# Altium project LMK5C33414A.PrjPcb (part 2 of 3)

## Sheet LMK5C33414A_DUT.SchDoc
size 431 x 279 mm; Date: Not shown in title block; ApprovedBy: Not shown in title block; CheckedBy: Not shown in title block; Author: Not shown in title block; CompanyName: Not shown in title block; Engineer: Not shown in title block; Organization: Not shown in title block; Address1: Not shown in title block; Address2: Not shown in title block; Address3: Not shown in title block; Address4: Not shown in title block; DocumentNumber: 2; Revision: Use project parameter SCH_Rev; SheetNumber: 2; SheetTotal: 3; PageSetup: Record=PageOptions¦CenterHorizontal=True¦CenterVertical=True¦PrintScale=1.00¦XCorrection=1.00¦YCorrection=1.00¦PrintKind=0¦BorderSize=5000000¦LeftOffset=0¦BottomOffset=0¦Orientation=2¦PaperLength=1000¦PaperWidth=1000¦Scale=100¦PaperSource=15¦PrintQuality=600¦MediaType=1¦DitherType=10¦PaperKind=Letter¦PrintScaleMode=1
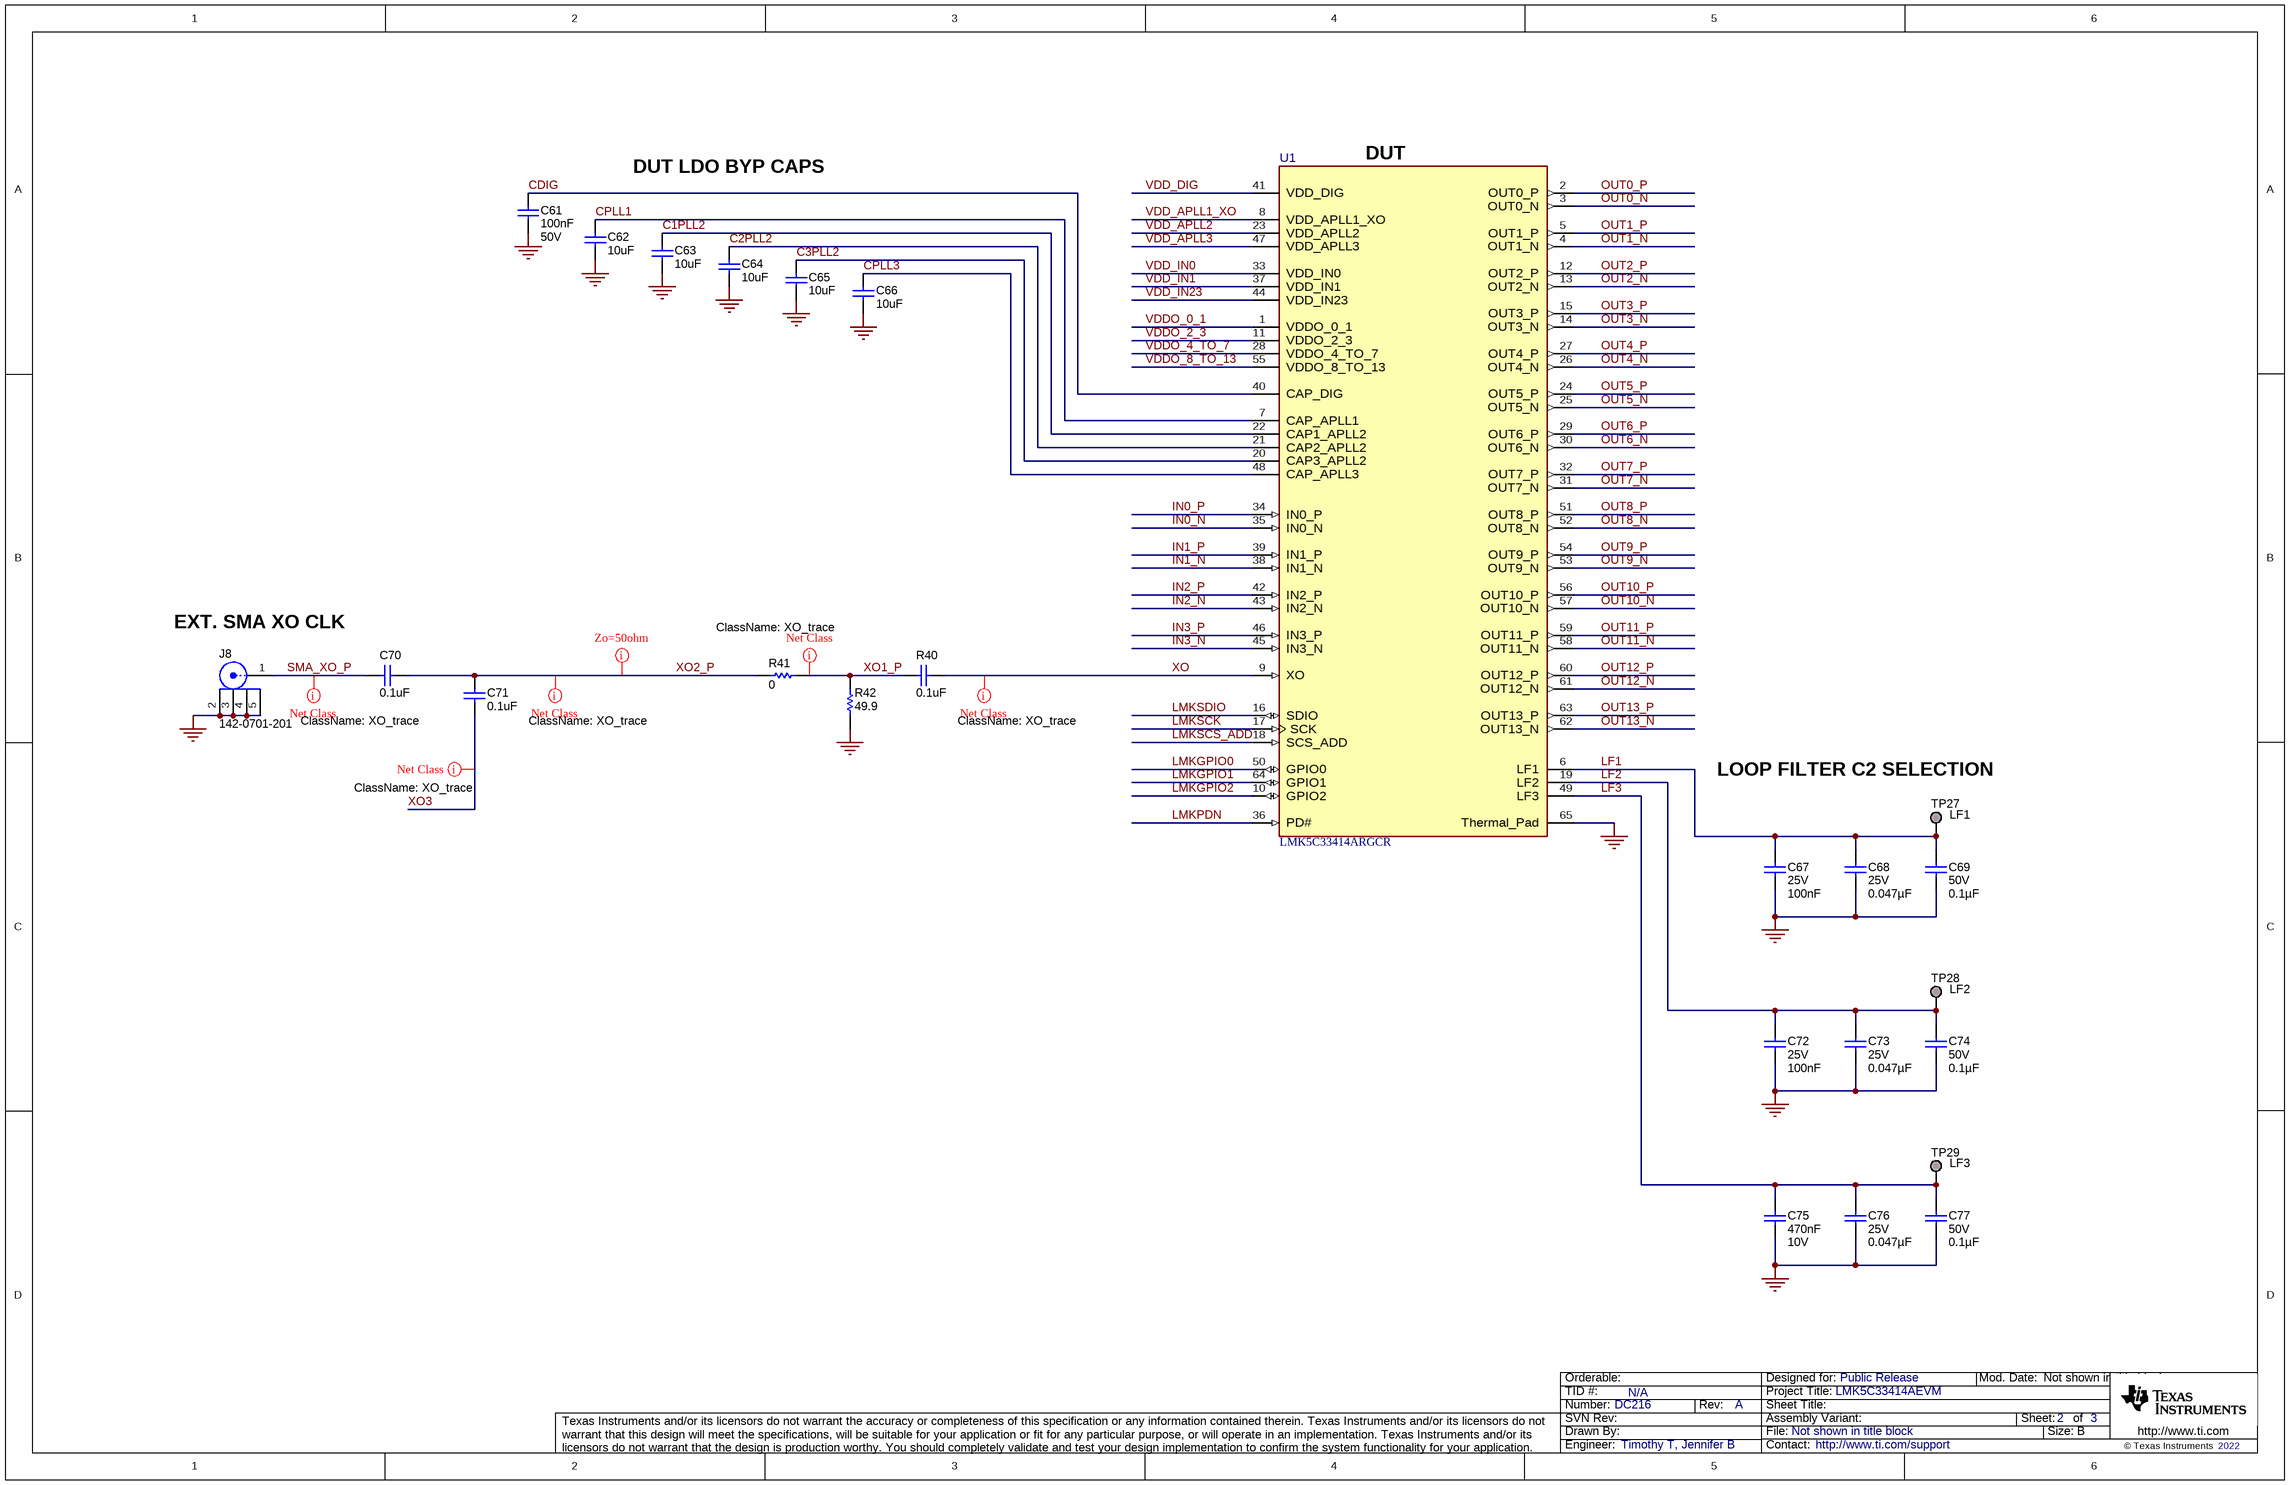
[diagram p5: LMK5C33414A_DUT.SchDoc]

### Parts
C61  Cap_F: 100nF  VDC_V: 50V  [0603L]  (hidden comment: C1608X7R1H104K080AA)
C62  ValueDisplayed: 10uF  [0603L]  (hidden comment: Capacitor)
C63  ValueDisplayed: 10uF  [0603L]  (hidden comment: Capacitor)
C64  ValueDisplayed: 10uF  [0603L]  (hidden comment: Capacitor)
C65  ValueDisplayed: 10uF  [0603L]  (hidden comment: Capacitor)
C66  ValueDisplayed: 10uF  [0603L]  (hidden comment: Capacitor)
C67  VDC_V: 25V  Cap_F: 100nF  [0603]  (hidden comment: C0603C104J3RACTU)
C68  VDC_V: 25V  ValueDisplayed: 0.047µF  [0805_150]  (hidden comment: C0805C473J3GACTU)
C69  VDC_V: 50V  ValueDisplayed: 0.1µF  [1210_280]  (hidden comment: C3225C0G1H104J250AA)
C70  ValueDisplayed: 0.1uF  [0603S]  (hidden comment: C0603C104J3RACTU)
C71  ValueDisplayed: 0.1uF  [0603S]  (hidden comment: C0603C104J3RACTU)
C72  VDC_V: 25V  Cap_F: 100nF  [0603]  (hidden comment: C0603C104J3RACTU)
C73  VDC_V: 25V  ValueDisplayed: 0.047µF  [0805_150]  (hidden comment: Capacitor)
C74  VDC_V: 50V  ValueDisplayed: 0.1µF  [1210_280]  (hidden comment: C3225C0G1H104J250AA)
C75  Cap_F: 470nF  VDC_V: 10V  [0603]  (hidden comment: GRM188R71A474KA61D)
C76  VDC_V: 25V  ValueDisplayed: 0.047µF  [0805_150]  (hidden comment: Capacitor)
C77  VDC_V: 50V  ValueDisplayed: 0.1µF  [1210_280]  (hidden comment: C3225C0G1H104J250AA)
J8  142-0701-201  [Johnson_142-0701-20x]
R40  ValueDisplayed: 0.1uF  [0603S]  (hidden comment: Capacitor)
R41  value 0  [0603S]  (hidden comment: Resistor)
R42  ValueDisplayed: 49.9  [0603S]  (hidden comment: Resistor)
TP27  LF1  [TP_SM_1MM]  (no BOM)
TP28  LF2  [TP_SM_1MM]  (no BOM)
TP29  LF3  [TP_SM_1MM]  (no BOM)
U1  LMK5C33414ARGCR  [RGC0064E-MFG]

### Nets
GND: C61.2 C62.2 C63.2 C64.2 C65.2 C66.2 C67.2 C68.1 C69.2 C72.2 C73.1 C74.2 C75.2 C76.1 C77.2 J8.2 J8.3 J8.4 J8.5 R42.1 U1.65(Thermal_Pad)
C1PLL2: C63.1 U1.22(CAP1_APLL2)
C2PLL2: C64.1 U1.21(CAP2_APLL2)
C3PLL2: C65.1 U1.20(CAP3_APLL2)
CDIG: C61.1 U1.40(CAP_DIG)
CPLL1: C62.1 U1.7(CAP_APLL1)
CPLL3: C66.1 U1.48(CAP_APLL3)
IN0_N: U1.35(IN0_N)
IN0_P: U1.34(IN0_P)
IN1_N: U1.38(IN1_N)
IN1_P: U1.39(IN1_P)
IN2_N: U1.43(IN2_N)
IN2_P: U1.42(IN2_P)
IN3_N: U1.45(IN3_N)
IN3_P: U1.46(IN3_P)
LF1: C67.1 C68.2 C69.1 TP27.1 U1.6(LF1)
LF2: C72.1 C73.2 C74.1 TP28.1 U1.19(LF2)
LF3: C75.1 C76.2 C77.1 TP29.1 U1.49(LF3)
LMKGPIO0: U1.50(GPIO0)
LMKGPIO1: U1.64(GPIO1)
LMKGPIO2: U1.10(GPIO2)
LMKPDN: U1.36(PD#)
LMKSCK: U1.17(SCK)
LMKSCS_ADD: U1.18(SCS_ADD)
LMKSDIO: U1.16(SDIO)
OUT0_N: U1.3(OUT0_N)
OUT0_P: U1.2(OUT0_P)
OUT1_N: U1.4(OUT1_N)
OUT1_P: U1.5(OUT1_P)
OUT2_N: U1.13(OUT2_N)
OUT2_P: U1.12(OUT2_P)
OUT3_N: U1.14(OUT3_N)
OUT3_P: U1.15(OUT3_P)
OUT4_N: U1.26(OUT4_N)
OUT4_P: U1.27(OUT4_P)
OUT5_N: U1.25(OUT5_N)
OUT5_P: U1.24(OUT5_P)
OUT6_N: U1.30(OUT6_N)
OUT6_P: U1.29(OUT6_P)
OUT7_N: U1.31(OUT7_N)
OUT7_P: U1.32(OUT7_P)
OUT8_N: U1.52(OUT8_N)
OUT8_P: U1.51(OUT8_P)
OUT9_N: U1.53(OUT9_N)
OUT9_P: U1.54(OUT9_P)
OUT10_N: U1.57(OUT10_N)
OUT10_P: U1.56(OUT10_P)
OUT11_N: U1.58(OUT11_N)
OUT11_P: U1.59(OUT11_P)
OUT12_N: U1.61(OUT12_N)
OUT12_P: U1.60(OUT12_P)
OUT13_N: U1.62(OUT13_N)
OUT13_P: U1.63(OUT13_P)
SMA_XO_P: C70.1 J8.1
VDD_APLL1_XO: U1.8(VDD_APLL1_XO)
VDD_APLL2: U1.23(VDD_APLL2)
VDD_APLL3: U1.47(VDD_APLL3)
VDD_DIG: U1.41(VDD_DIG)
VDD_IN0: U1.33(VDD_IN0)
VDD_IN1: U1.37(VDD_IN1)
VDD_IN23: U1.44(VDD_IN23)
VDDO_0_1: U1.1(VDDO_0_1)
VDDO_2_3: U1.11(VDDO_2_3)
VDDO_4_TO_7: U1.28(VDDO_4_TO_7)
VDDO_8_TO_13: U1.55(VDDO_8_TO_13)
XO: R40.2 U1.9(XO)
XO1_P: R40.1 R41.2 R42.2
XO2_P: C70.2 C71.1 R41.1
XO3: C71.2

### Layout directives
rule Impedance Constraint [Min = 45.00    Max = 55.00    ]: XO2_P
net class XO_trace: SMA_XO_P, XO, XO1_P, XO2_P, XO3

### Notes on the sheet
- DUT LDO BYP CAPS
- (near U1) DUT
- EXT. SMA XO CLK
- (near TP27) LOOP FILTER C2 SELECTION

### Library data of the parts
C61 = CMP-0007044-5: CAP, CERM, 0.1 uF, 50 V, +/- 10%, X7R, 0603; Manufacturer: TDK; Polarized: N; Value: 0.1uF; U/M: EA; ESR_ohm: 0.0296; Value1: 0.0296 ohm; IRMS_A: 9.7199dA; TaMin_C: -55°C; TaMax_C: 125°C; Cap_Case: 0603; SizeArea_mm2: 1.28; SizeAreaWB_mm2: 4.68; SizeX_mm: 1.6; SizeY_mm: 0.8; SizeZ_mm: 1; AEC Category: Q200
C62-C66 = CMP-0007003-5: CAP, CERM, 10 uF, 10 V, +/- 20%, X5R, 0603; PartNumber: C1608X5R1A106M080AC; Manufacturer: TDK; Polarized: N; Value: 10uF; U/M: EA; Cap_F: 10µF; ESR_ohm: 7.8m; Value1: 0.0078 ohm; VDC_V: 10V; IRMS_A: 1.85A; TaMin_C: -55°C; TaMax_C: 85°C; Cap_Case: 0603; SizeArea_mm2: 1.28; SizeAreaWB_mm2: 4.68; SizeX_mm: 1.6; SizeY_mm: 0.8; SizeZ_mm: 1; AEC Category: Q200
C67 C72 = CMP-0006856-6: CAP, CERM, 0.1 uF, 25 V, +/- 5%, X7R, 0603; Manufacturer: Kemet; Polarized: N; TaMax_C: 125°C; TaMin_C: -55°C; Value: 0.1uF; Value1: Unknown; U/M: EA; AEC Category: Q200; SizeArea_mm2: 1.28; SizeAreaWB_mm2: 4.68; SizeX_mm: 1.6; SizeY_mm: 0.8; SizeZ_mm: 1
C68 = CMP-0078743-1: CAP, CERM, 0.047 µF, 25 V,+/- 5%, C0G/NP0, AEC-Q200 Grade 1, 0805; Manufacturer: Kemet; Polarized: N; TaMax_C: 125°C; TaMin_C: -55°C; Cap_F: 47nF; Value: 0.047uF; U/M: EA; SizeArea_mm2: 2.5; SizeAreaWB_mm2: 6.75; SizeX_mm: 2; SizeY_mm: 1.25; SizeZ_mm: 1.5; AEC Category: Q200; AEC Qualified: Y; AEC Grade: 1; Green_REACh: Incomplete; Green_Lifecycle: Not Set
C69 C74 C77 = CMP-0081101-1: CAP, CERM, 0.1 µF, 50 V,+/- 5%, C0G/NP0, 1210; Manufacturer: TDK; TaMin_C: -55°C; Polarized: N; SizeAreaWB_mm2: 14.7; U/M: EA; Value: 0.1uF; TaMax_C: 125°C; SizeZ_mm: 2.8; SizeX_mm: 3.2; SizeY_mm: 2.5; Cap_Case: 1210; SizeArea_mm2: 8; Cap_F: 100nF; AEC Category: Q200; Green_Lifecycle: Active; Green_REACh: Incomplete
C70 C71 = CMP-0006856-6: CAP, CERM, 0.1 uF, 25 V, +/- 5%, X7R, 0603; Manufacturer: Kemet; TaMin_C: -55°C; Polarized: N; SizeAreaWB_mm2: 4.68; Value1: Unknown; U/M: EA; Value: 0.1uF; TaMax_C: 125°C; SizeZ_mm: 1; SizeX_mm: 1.6; SizeY_mm: 0.8; Cap_Case: 0603; Value2: 25V; SizeArea_mm2: 1.28; Cap_F: 100nF; AEC Category: Q200
C73 C76 = CMP-0078743-1: CAP, CERM, 0.047 µF, 25 V,+/- 5%, C0G/NP0, AEC-Q200 Grade 1, 0805; Manufacturer: Kemet; PartNumber: C0805C473J3GACTU; Polarized: N; TaMax_C: 125°C; TaMin_C: -55°C; Cap_F: 47nF; Value: 0.047uF; U/M: EA; SizeArea_mm2: 2.5; SizeAreaWB_mm2: 6.75; SizeX_mm: 2; SizeY_mm: 1.25; SizeZ_mm: 1.5; AEC Category: Q200; AEC Qualified: Y; AEC Grade: 1; Green_REACh: Incomplete; Green_Lifecycle: Not Set
C75 = CMP-0007373-4: CAP, CERM, 0.47 uF, 10 V, +/- 10%, X7R, 0603; Manufacturer: MuRata; Polarized: N; Value: 0.47uF; U/M: EA; Value1: Unknown; TaMin_C: -55°C; TaMax_C: 125°C; SizeArea_mm2: 1.28; SizeAreaWB_mm2: 4.68; SizeX_mm: 1.6; SizeY_mm: 0.8; SizeZ_mm: 1; AEC Category: Q200
J8 = CMP-0055819-1: Connector, SMA, TH; Manufacturer: Cinch Connectivity; CNHeader: FALSE; CT: TRUE; Green_Lifecycle: Not Set; Green_REACh: Incomplete
R40 = CMP-0006856-6: CAP, CERM, 0.1 uF, 25 V, +/- 5%, X7R, 0603; Manufacturer: Kemet; PartNumber: C0603C104J3RACTU; VDC_V: 25V; Value: 0.1uF; Value1: Unknown; U/M: EA; Polarized: N; Cap_F: 100nF; TaMin_C: -55°C; TaMax_C: 125°C; Cap_Case: 0603; SizeArea_mm2: 1.28; SizeAreaWB_mm2: 4.68; SizeX_mm: 1.6; SizeY_mm: 0.8; SizeZ_mm: 1; AEC Category: Q200
R41 = CMP-0025697-4: RES, 0, 5%, 0.1 W, AEC-Q200 Grade 0, 0603; Manufacturer: Vishay-Dale; PartNumber: CRCW06030000Z0EA; VDC_V: 75V; Power_W: 100mW; Value_Code: 0000; Value2: 0.1W; EIA_Code: E24; TempCo: 200 ppm/C; AEC Category: Q200; AEC Qualified: Y; SizeArea_mm2: 1.28; SizeX_mm: 1.6; SizeY_mm: 0.8; SizeZ_mm: 1
R42 = CMP-0022448-4: RES, 49.9, 1%, 0.1 W, AEC-Q200 Grade 0, 0603; PartNumber: CRCW060349R9FKEA; Manufacturer: Vishay-Dale; Value: 49.9; Value_Code: 49R9; Power_W: 100mW; Value2: 0.1W; VDC_V: 75V; TempCo: 100 ppm/C; EIA_Code: E96; AEC Category: Q200; AEC Qualified: Y; AEC Grade: 0; SizeArea_mm2: 1.28; SizeX_mm: 1.6; SizeY_mm: 0.8; SizeZ_mm: 1
TP27-TP29 = CMP-0003825-1: 1mm Test Point, SMT; Manufacturer: Any
U1 = CMP-0088784-1: Ultra-Low Jitter Clock Synchronizer with JESD204B for Wireless Communications; Part Number: LMK5C33414RGCR; Manufacturer: Texas Instruments; TJmax_C: +135°C; Pll: YES; Min Supply Voltage: 3.135V; AEC Qualified: No; Max Frequency: 2.9491GHz; Interface: I2C,SPI; SizeZ_mm: 1mm; Standoff Height: 0mm; Number Of Outputs: 14; Max Supply Voltage: 3.465V

## Sheet LMK5C33414A_Logic.SchDoc
size 431 x 279 mm; Date: Not shown in title block; ApprovedBy: Not shown in title block; CheckedBy: Not shown in title block; Author: Not shown in title block; CompanyName: Not shown in title block; Engineer: Not shown in title block; Organization: Not shown in title block; Address1: Not shown in title block; Address2: Not shown in title block; Address3: Not shown in title block; Address4: Not shown in title block; DocumentNumber: 2; Revision: Use project parameter SCH_Rev; SheetNumber: 2; SheetTotal: 3; PageSetup: Record=PageOptions¦CenterHorizontal=True¦CenterVertical=True¦PrintScale=1.00¦XCorrection=1.00¦YCorrection=1.00¦PrintKind=0¦BorderSize=5000000¦LeftOffset=0¦BottomOffset=0¦Orientation=2¦PaperLength=1000¦PaperWidth=1000¦Scale=100¦PaperSource=15¦PrintQuality=600¦MediaType=1¦DitherType=10¦PaperKind=Letter¦PrintScaleMode=1
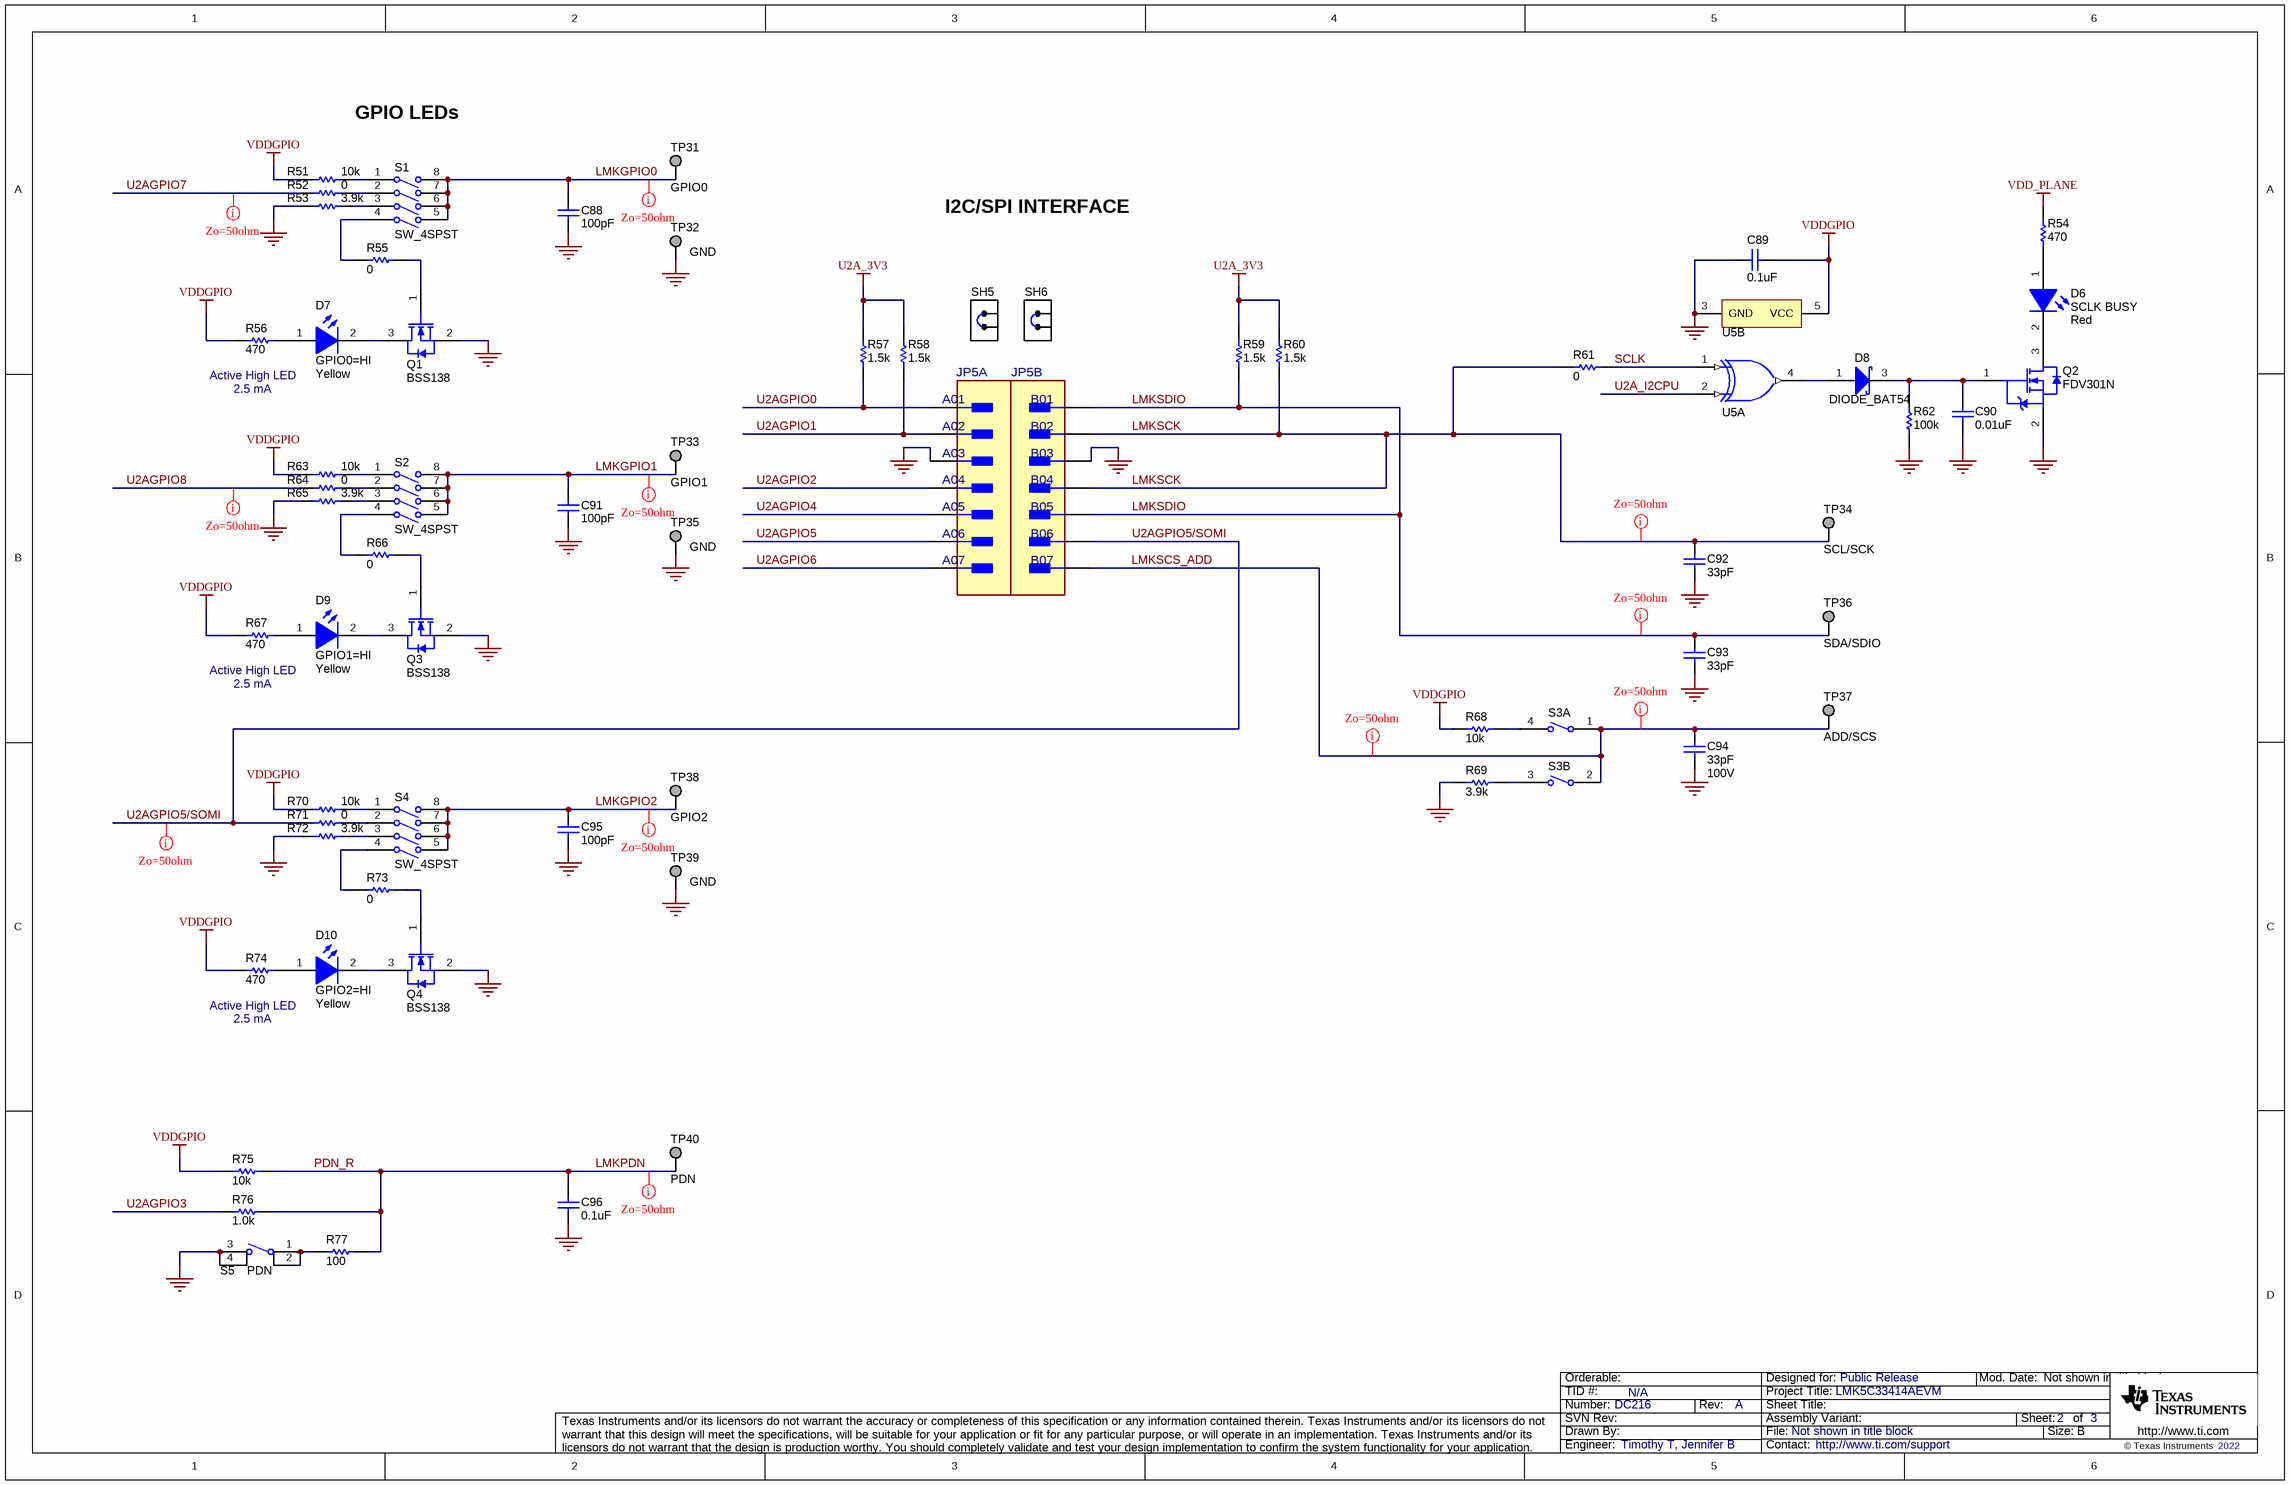
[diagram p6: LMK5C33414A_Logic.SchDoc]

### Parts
C88  ValueDisplayed: 100pF  [0603]  (hidden comment: Capacitor)
C89  ValueDisplayed: 0.1uF  [0603]  (hidden comment: Capacitor)
C90  ValueDisplayed: 0.01uF  [0603]  (hidden comment: Capacitor)
C91  ValueDisplayed: 100pF  [0603]  (hidden comment: Capacitor)
C92  ValueDisplayed: 33pF  [0603]  (hidden comment: Capacitor)
C93  ValueDisplayed: 33pF  [0603]  (hidden comment: Capacitor)
C94  ValueDisplayed: 33pF  VDC_V: 100V  [0603]  (hidden comment: 06031A330JAT2A)
C95  ValueDisplayed: 100pF  [0603]  (hidden comment: Capacitor)
C96  ValueDisplayed: 0.1uF  [0603]  (hidden comment: C0603C104J3RACTU)
D6  SCLK BUSY  value Red  [LED_LTST-C170_Red]
D7  GPIO0=HI  value Yellow  [LED_LTST-C170]
D8  DIODE_BAT54  [SOT-23]
D9  GPIO1=HI  value Yellow  [LED_LTST-C170]
D10  GPIO2=HI  value Yellow  [LED_LTST-C170]
JP5  54202-G0807LF  [FP-54202-G0807LF_HDR14-MFG]  (value not drawn)  (parts A,B of 2)
Q1  BSS138  [SOT-23]
Q2  FDV301N  [SOT-23]
Q3  BSS138  [SOT-23]
Q4  BSS138  [SOT-23]
R51  ValueDisplayed: 10k  [0603]  (hidden comment: Resistor)
R52  ValueDisplayed: 0  [0603]  (hidden comment: Resistor)
R53  ValueDisplayed: 3.9k  [0603]  (hidden comment: CRCW06033K90JNEA)
R54  ValueDisplayed: 470  [0603]  (hidden comment: Resistor)
R55  ValueDisplayed: 0  [0603L]  (hidden comment: Resistor)
R56  ValueDisplayed: 470  [0603]  (hidden comment: Resistor)
R57  ValueDisplayed: 1.5k  [0603]  (hidden comment: Resistor)
R58  ValueDisplayed: 1.5k  [0603]  (hidden comment: Resistor)
R59  ValueDisplayed: 1.5k  [0603]  (hidden comment: Resistor)
R60  ValueDisplayed: 1.5k  [0603]  (hidden comment: Resistor)
R61  ValueDisplayed: 0  [0603]  (hidden comment: Resistor)
R62  ValueDisplayed: 100k  [0603]  (hidden comment: Resistor)
R63  ValueDisplayed: 10k  [0603]  (hidden comment: Resistor)
R64  ValueDisplayed: 0  [0603]  (hidden comment: Resistor)
R65  ValueDisplayed: 3.9k  [0603]  (hidden comment: CRCW06033K90JNEA)
R66  ValueDisplayed: 0  [0603L]  (hidden comment: Resistor)
R67  ValueDisplayed: 470  [0603]  (hidden comment: Resistor)
R68  ValueDisplayed: 10k  [0603]  (hidden comment: Resistor)
R69  ValueDisplayed: 3.9k  [0603]  (hidden comment: Resistor)
R70  ValueDisplayed: 10k  [0603]  (hidden comment: Resistor)
R71  ValueDisplayed: 0  [0603]  (hidden comment: Resistor)
R72  ValueDisplayed: 3.9k  [0603]  (hidden comment: CRCW06033K90JNEA)
R73  ValueDisplayed: 0  [0603L]  (hidden comment: Resistor)
R74  ValueDisplayed: 470  [0603]  (hidden comment: Resistor)
R75  ValueDisplayed: 10k  [0603]  (hidden comment: Resistor)
R76  ValueDisplayed: 1.0k  [0603]  (hidden comment: Resistor)
R77  ValueDisplayed: 100  [0603]  (hidden comment: ESR03EZPJ101)
S1  SW_4SPST  [SW_219-4LPST]
S2  SW_4SPST  [SW_219-4LPST]
S3  SW_219-2LPST  [SW_219-2LPST]  (value not drawn)  (parts A,B of 2)
S4  SW_4SPST  [SW_219-4LPST]
S5  PDN  [SW_FSM4JSMA]
SH5  SNT-100-BK-G  [SNT-100-BK-G]  (value not drawn)
SH6  SNT-100-BK-G  [SNT-100-BK-G]  (value not drawn)
TP31  GPIO0  [Keystone_5019]
TP32  GND  [Keystone_5019]
TP33  GPIO1  [Keystone_5019]
TP34  SCL/SCK  [Keystone_5019]
TP35  GND  [Keystone_5019]
TP36  SDA/SDIO  [Keystone_5019]
TP37  ADD/SCS  [Keystone_5019]
TP38  GPIO2  [Keystone_5019]
TP39  GND  [Keystone_5019]
TP40  PDN  [Keystone_5019]
U5  TI-XOR-1-2IN-5  [DBV0005A_N]  (value not drawn)  (parts A,B of 2)

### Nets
GND: C88.2 C89.1 C90.2 C91.2 C92.2 C93.2 C94.2 C95.2 C96.2 JP5.A03 JP5.B03 Q1.2(S) Q2.2(S) Q3.2(S) Q4.2(S) R53.1 R62.1 R65.1 R69.1 R72.1 S5.3 S5.4 TP32.1 TP35.1 TP39.1 U5.3(GND)
U2A_3V3: R57.2 R58.2 R59.2 R60.2
VDD_PLANE: R54.2
VDDGPIO: C89.2 R51.1 R56.2 R63.1 R67.2 R68.1 R70.1 R74.2 R75.1 U5.5(VCC)
LMKGPIO0: C88.1 S1.5(B4) S1.6(B3) S1.7(B2) S1.8(B1) TP31.1
LMKGPIO1: C91.1 S2.5(B4) S2.6(B3) S2.7(B2) S2.8(B1) TP33.1
LMKGPIO2: C95.1 S4.5(B4) S4.6(B3) S4.7(B2) S4.8(B1) TP38.1
LMKPDN: C96.1 R75.2 R76.2 R77.1 TP40.1  [also labelled PDN_R]
LMKSCK: C92.1 JP5.B02 JP5.B04 R60.1 R61.1 TP34.1
LMKSCS_ADD: C94.1 JP5.B07 S3.1(1A) S3.2(2A) TP37.1
LMKSDIO: C93.1 JP5.B01 JP5.B05 R59.1 TP36.1
SCLK: R61.2 U5.1(A)
U2A_I2CPU: U5.2(B)
U2AGPIO0: JP5.A01 R57.1
U2AGPIO1: JP5.A02 R58.1
U2AGPIO2: JP5.A04
U2AGPIO3: R76.1
U2AGPIO4: JP5.A05
U2AGPIO5: JP5.A06
U2AGPIO5/SOMI: JP5.B06 R71.2
U2AGPIO6: JP5.A07
U2AGPIO7: R52.1
U2AGPIO8: R64.1
NetC90_1: C90.1 D8.3(K) Q2.1(G) R62.2
NetD6_1: D6.1(A) R54.1
NetD6_2: D6.2(K) Q2.3(D)
NetD7_1: D7.1(A) R56.1
NetD7_2: D7.2(K) Q1.3(D)
NetD8_1: D8.1(A) U5.4(Y)
NetD9_1: D9.1(A) R67.1
NetD9_2: D9.2(K) Q3.3(D)
NetD10_1: D10.1(A) R74.1
NetD10_2: D10.2(K) Q4.3(D)
NetQ1_1: Q1.1(G) R55.2
NetQ3_1: Q3.1(G) R66.2
NetQ4_1: Q4.1(G) R73.2
NetR51_2: R51.2 S1.1(A1)
NetR52_2: R52.2 S1.2(A2)
NetR53_2: R53.2 S1.3(A3)
NetR55_1: R55.1 S1.4(A4)
NetR63_2: R63.2 S2.1(A1)
NetR64_2: R64.2 S2.2(A2)
NetR65_2: R65.2 S2.3(A3)
NetR66_1: R66.1 S2.4(A4)
NetR68_2: R68.2 S3.4(1B)
NetR69_2: R69.2 S3.3(2B)
NetR70_2: R70.2 S4.1(A1)
NetR71_1: R71.1 S4.2(A2)
NetR72_2: R72.2 S4.3(A3)
NetR73_1: R73.1 S4.4(A4)
NetR77_2: R77.2 S5.1 S5.2

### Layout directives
rule Impedance Constraint [Min = 45.00    Max = 55.00    ]: LMKGPIO0, LMKGPIO1, LMKGPIO2, LMKPDN, LMKSCK, LMKSCS_ADD, LMKSDIO, U2AGPIO5/SOMI, U2AGPIO7, U2AGPIO8

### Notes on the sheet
- GPIO LEDs
- I2C/SPI INTERFACE
- Active High LED
  2.5 mA

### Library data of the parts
C88 C91 C95 = CMP-0006763-4: CAP, CERM, 100 pF, 50 V, +/- 5%, C0G/NP0, 0603; PartNumber: 06035A101JAT2A; Manufacturer: AVX; Polarized: N; Value: 100pF; U/M: EA; ESR_ohm: 1.19d; Value1: 0.119 ohm; VDC_V: 50V; TaMin_C: -55°C; TaMax_C: 125°C; AEC Category: Q200; SizeArea_mm2: 1.28; SizeAreaWB_mm2: 4.68; SizeX_mm: 1.6; SizeY_mm: 0.8; SizeZ_mm: 1
C89 = CMP-0006857-4: CAP, CERM, 0.1 uF, 16 V, +/- 5%, X7R, 0603; PartNumber: C0603C104J4RACTU; Manufacturer: Kemet; Polarized: N; Value: 0.1uF; U/M: EA; Cap_F: 100nF; Value1: Unknown; VDC_V: 16V; TaMin_C: -55°C; TaMax_C: 125°C; AEC Category: Q200; SizeArea_mm2: 1.28; SizeAreaWB_mm2: 4.68; SizeX_mm: 1.6; SizeY_mm: 0.8; SizeZ_mm: 1
C90 = CMP-0006850-4: CAP, CERM, 0.01 uF, 50 V, +/- 5%, X7R, 0603; PartNumber: C0603C103J5RACTU; Manufacturer: Kemet; Polarized: N; Value: 0.01uF; U/M: EA; Cap_F: 10nF; Value1: Unknown; VDC_V: 50V; TaMin_C: -55°C; TaMax_C: 125°C; SizeArea_mm2: 1.28; SizeAreaWB_mm2: 4.68; SizeX_mm: 1.6; SizeY_mm: 0.8; SizeZ_mm: 1; AEC Category: Q200
C92 C93 = CMP-0006722-4: CAP, CERM, 33 pF, 100 V, +/- 5%, C0G/NP0, 0603; PartNumber: 06031A330JAT2A; Manufacturer: AVX; Polarized: N; Value: 33pF; U/M: EA; ESR_ohm: 2.09d; Value1: 0.209 ohm; VDC_V: 100V; TaMin_C: -55°C; TaMax_C: 125°C; AEC Category: Q200; SizeArea_mm2: 1.28; SizeAreaWB_mm2: 4.68; SizeX_mm: 1.6; SizeY_mm: 0.8; SizeZ_mm: 1
C94 = CMP-0006722-4: CAP, CERM, 33 pF, 100 V, +/- 5%, C0G/NP0, 0603; Manufacturer: AVX; Polarized: N; Value: 33pF; U/M: EA; ESR_ohm: 2.09d; Value1: 0.209 ohm; TaMin_C: -55°C; TaMax_C: 125°C; AEC Category: Q200; SizeArea_mm2: 1.28; SizeAreaWB_mm2: 4.68; SizeX_mm: 1.6; SizeY_mm: 0.8; SizeZ_mm: 1
C96 = CMP-0006856-6: CAP, CERM, 0.1 uF, 25 V, +/- 5%, X7R, 0603; Manufacturer: Kemet; Polarized: N; Value: 0.1uF; U/M: EA; Cap_F: 100nF; Value1: Unknown; VDC_V: 25V; TaMin_C: -55°C; TaMax_C: 125°C; AEC Category: Q200; SizeArea_mm2: 1.28; SizeAreaWB_mm2: 4.68; SizeX_mm: 1.6; SizeY_mm: 0.8; SizeZ_mm: 1
D6 = CMP-0002829-2: LED, Red, SMD; Manufacturer: Lite-On; PartNumber: LTST-C170KRKT; Type: AlInGaP; Vf_V: 2V; Io_A: 20mA; Value1: W; U/M: EA; SizeAreaWB_mm2: 6.75; SizeArea_mm2: 2.5; SizeX_mm: 2; SizeY_mm: 1.25; SizeZ_mm: 1.2
D7 D9 D10 = CMP-0002862-2: LED, Yellow , SMD; Manufacturer: Lite-On; PartNumber: LTST-C170KSKT; Type: AlInGaP; Vf_V: 2V; Io_A: 20mA; Value1: W; SizeArea_mm2: 2.5; SizeAreaWB_mm2: 6.75; SizeX_mm: 2; SizeY_mm: 1.25; SizeZ_mm: 1.2
D8 = CMP-0028451-2: Diode, Schottky, 30 V, 0.2 A, SOT-23; PartNumber: BAT54-7-F; Manufacturer: Diodes Inc.; Vf_V: 6.5dV; Value: 30V; Value1: 0.2A; Value2: 0.65V; Io_A: 2dA; TJmax_C: 125°C; SizeAreaWB_mm2: 14; SizeArea_mm2: 7.5; SizeX_mm: 2.5; SizeY_mm: 3; SizeZ_mm: 1.1; AEC Category: Q101; Green_Lifecycle: Active; Green_REACh: Passed
JP5 = CMP-0088459-1: Connector Header Surface Mount 14 position 0.100" (2.54mm); Manufacturer: Amphenol ICC; Standoff Height: 1.01mm; Voltage_V: 1.5kV; Conn Gender: Male; ContactFinish: Gold,Nickel; AEC Qualified: No; SizeZ_mm: 9.98mm; Conn Orientation: Straight; Current_A: 3A; Row_Count: 2
Q1 Q3 Q4 = CMP-0000755-1: MOSFET, N-CH, 50 V, 0.22 A, SOT-23; Manufacturer: Fairchild Semiconductor; Alternate Manufacturer: None; U/M: EA; ChType: N; Value: 50V; Rdson45_ohm: 6; Value2: 1.7 nC; QgTyp_nC: 1.7; Vgs_V: 20V; IdsMax_A: 2.2dA; AEC Category: Q101; SizeArea_mm2: 7.5; SizeAreaWB_mm2: 14; SizeX_mm: 2.5; SizeY_mm: 3; SizeZ_mm: 1.1
Q2 = CMP-0000281-1: MOSFET, N-CH, 25 V, 0.22 A, SOT-23; Manufacturer: Fairchild Semiconductor; Alternate Manufacturer: None; U/M: EA; ChType: N; Value: 25V; Rdson45_ohm: 4; Value2: 0.49 nC; QgTyp_nC: 0.49; Vgs_V: 8V; IdsMax_A: 2.2dA; SizeAreaWB_mm2: 14; SizeArea_mm2: 7.5; SizeX_mm: 2.5; SizeY_mm: 3; SizeZ_mm: 1.1; AEC Category: Q101
R51 R63 R68 R70 R75 = CMP-0025701-4: RES, 10 k, 5%, 0.1 W, AEC-Q200 Grade 0, 0603; PartNumber: CRCW060310K0JNEA; Manufacturer: Vishay-Dale; Value: 10k; Value_Code: 10k0; Power_W: 100mW; Value2: 0.1W; VDC_V: 75V; TempCo: 200 ppm/C; EIA_Code: E24; SizeArea_mm2: 1.28; SizeX_mm: 1.6; SizeY_mm: 0.8; SizeZ_mm: 1; AEC Category: Q200; AEC Qualified: Y; AEC Grade: 0
R52 R61 R64 R71 = CMP-0025697-4: RES, 0, 5%, 0.1 W, AEC-Q200 Grade 0, 0603; PartNumber: CRCW06030000Z0EA; Manufacturer: Vishay-Dale; Value: 0; Value_Code: 0000; Power_W: 100mW; Value2: 0.1W; VDC_V: 75V; TempCo: 200 ppm/C; EIA_Code: E24; AEC Category: Q200; AEC Qualified: Y; SizeArea_mm2: 1.28; SizeX_mm: 1.6; SizeY_mm: 0.8; SizeZ_mm: 1
R53 R65 R72 = CMP-0025799-4: RES, 3.9 k, 5%, 0.1 W, AEC-Q200 Grade 0, 0603; Manufacturer: Vishay-Dale; Value: 3.9k; Value_Code: 3k90; Power_W: 100mW; Value2: 0.1W; VDC_V: 75V; TempCo: 200 ppm/C; EIA_Code: E24; SizeArea_mm2: 1.28; SizeX_mm: 1.6; SizeY_mm: 0.8; SizeZ_mm: 1; AEC Category: Q200; AEC Qualified: Y; AEC Grade: 0
R54 R56 R67 R74 = CMP-0025813-4: RES, 470, 5%, 0.1 W, AEC-Q200 Grade 0, 0603; PartNumber: CRCW0603470RJNEA; Manufacturer: Vishay-Dale; Value: 470; Value_Code: 470R; Power_W: 100mW; Value2: 0.1W; VDC_V: 75V; TempCo: 200 ppm/C; EIA_Code: E24; SizeArea_mm2: 1.28; SizeX_mm: 1.6; SizeY_mm: 0.8; SizeZ_mm: 1; AEC Category: Q200; AEC Qualified: Y; AEC Grade: 0
R55 R66 R73 = CMP-0025697-4: RES, 0, 5%, 0.1 W, AEC-Q200 Grade 0, 0603; PartNumber: CRCW06030000Z0EA; Manufacturer: Vishay-Dale; Value: 0; Value_Code: 0000; Power_W: 100mW; Value2: 0.1W; VDC_V: 75V; TempCo: 200 ppm/C; EIA_Code: E24; SizeArea_mm2: 1.28; SizeX_mm: 1.6; SizeY_mm: 0.8; SizeZ_mm: 1; AEC Category: Q200; AEC Qualified: Y
R57-R60 = CMP-0025733-4: RES, 1.5 k, 5%, 0.1 W, AEC-Q200 Grade 0, 0603; PartNumber: CRCW06031K50JNEA; Manufacturer: Vishay-Dale; Value: 1.5k; Value_Code: 1k50; Power_W: 100mW; Value2: 0.1W; VDC_V: 75V; TempCo: 200 ppm/C; EIA_Code: E24; SizeArea_mm2: 1.28; SizeX_mm: 1.6; SizeY_mm: 0.8; SizeZ_mm: 1; AEC Category: Q200; AEC Qualified: Y; AEC Grade: 0
R62 = CMP-0025698-4: RES, 100 k, 5%, 0.1 W, AEC-Q200 Grade 0, 0603; PartNumber: CRCW0603100KJNEA; Manufacturer: Vishay-Dale; Value: 100k; Power_W: 100mW; Value2: 0.1W; VDC_V: 75V; TempCo: 200 ppm/C; EIA_Code: E24; SizeArea_mm2: 1.28; SizeX_mm: 1.6; SizeY_mm: 0.8; SizeZ_mm: 1; AEC Category: Q200; AEC Qualified: Y; AEC Grade: 0
R69 = CMP-0025799-4: RES, 3.9 k, 5%, 0.1 W, AEC-Q200 Grade 0, 0603; PartNumber: CRCW06033K90JNEA; Manufacturer: Vishay-Dale; Value: 3.9k; Value_Code: 3k90; Power_W: 100mW; Value2: 0.1W; VDC_V: 75V; TempCo: 200 ppm/C; EIA_Code: E24; SizeArea_mm2: 1.28; SizeX_mm: 1.6; SizeY_mm: 0.8; SizeZ_mm: 1; AEC Category: Q200; AEC Qualified: Y; AEC Grade: 0
R76 = CMP-0025729-4: RES, 1.0 k, 5%, 0.1 W, AEC-Q200 Grade 0, 0603; PartNumber: CRCW06031K00JNEA; Manufacturer: Vishay-Dale; Value: 1.0k; Res_ohm: 1k; Value_Code: 1k00; Power_W: 100mW; Value2: 0.1W; VDC_V: 75V; TempCo: 200 ppm/C; EIA_Code: E24; SizeArea_mm2: 1.28; SizeX_mm: 1.6; SizeY_mm: 0.8; SizeZ_mm: 1; AEC Category: Q200; AEC Qualified: Y; AEC Grade: 0
R77 = CMP-0025882-3: RES, 100, 5%, 0.25 W, AEC-Q200 Grade 0, 0603; Manufacturer: Rohm; Value: 100; Value_Code: 100R; Power_W: 250mW; Value2: 0.25W; VDC_V: 150V; TempCo: 200 ppm/C; EIA_Code: E24; SizeArea_mm2: 1.28; SizeX_mm: 1.6; SizeY_mm: 0.8; SizeZ_mm: 1; AEC Category: Q200; AEC Qualified: Y; AEC Grade: 0; U/M: EA
S1 S2 S4 = CMP-0002176-2: Switch, SPST 4 Pos, Top Actuated, SMT; PartNumber: 219-4LPST; Manufacturer: CTS Electrocomponents; VDC_V: 50V; SwitchFunction: Off-On; PositionCount: 4; CurrentRating_mA: 100A
S3 = CMP-0002127-2: Switch, Slide, SPST 2 poles, SMT; Manufacturer: CTS Electrocomponents; VDC_V: 20V; SwitchFunction: Off-On; PositionCount: 2; CurrentRating_mA: 100A
S5 = CMP-0002134-3: Switch, Tactile, SPST-NO, 0.05A, 12V, SMT; PartNumber: FSM4JSMA; Manufacturer: TE Connectivity; CurrentRating_mA: 50A; PositionCount: 1; SwitchFunction: Off-Mom
SH5 SH6 = CMP-0003623-3: Shunt, 100mil, Gold plated, Black; Manufacturer: Samtec; Alternate Manufacturer: 3M; Alternate PartNumber: 969102-0000-DA; Value: 1x2; Note: You can "mate" this to a header by matching the designator.  i.e. use SH-J3 for header J3
TP31-TP40 = CMP-0055162-1: Test Point, Miniature, SMT; Manufacturer: Keystone; PartNumber: 5019; CNHeader: FALSE; Green_Lifecycle: Active; Green_REACh: Passed; CT: TRUE
U5 = CMP-0052046-2: Single 2-Input Exclusive-OR Gate, DBV0005A (SOT-23-5); PartNumber: SN74LVC1G86DBVR; Manufacturer: Texas Instruments; Generic Part Number: SN74LVC1G86; SizeArea_mm2: 8.12; SizeAreaWB_mm2: 14.82; SizeX_mm: 2.8; SizeY_mm: 2.9; SizeZ_mm: 1.45; CompType: IC; 3-State Output: No; AEC Category: Q200; AEC Qualified: N; Bits(#): 1; F @ Nom Voltage(Max)(Mhz): 150; Gate Type: XOR; ICC @ Nom Voltage(Max)(mA): 0.01; Input Type: CMOS/TTL; Logic: True; Output Drive (IOL/IOH)(Max)(mA): 32/-32; Output Type: CMOS; Rating: Catalog; tpd @ Nom Voltage(Max)(ns): 9.9,5.5,5,4; VCC(Max)(V): 5.5; VCC(Min)(V): 1.65; Voltage(Nom)(V): 1.8,2.5,3.3,5

## Sheet LMK5C33414A_Outputs_A.SchDoc
size 431 x 279 mm; Date: Not shown in title block; ApprovedBy: Not shown in title block; CheckedBy: Not shown in title block; Author: Not shown in title block; CompanyName: Not shown in title block; Engineer: Not shown in title block; Organization: Not shown in title block; Address1: Not shown in title block; Address2: Not shown in title block; Address3: Not shown in title block; Address4: Not shown in title block; DocumentNumber: 2; Revision: Use project parameter SCH_Rev; SheetNumber: 2; SheetTotal: 3; PageSetup: Record=PageOptions¦CenterHorizontal=True¦CenterVertical=True¦PrintScale=1.00¦XCorrection=1.00¦YCorrection=1.00¦PrintKind=0¦BorderSize=5000000¦LeftOffset=0¦BottomOffset=0¦Orientation=2¦PaperLength=1000¦PaperWidth=1000¦Scale=100¦PaperSource=15¦PrintQuality=600¦MediaType=1¦DitherType=10¦PaperKind=Letter¦PrintScaleMode=1
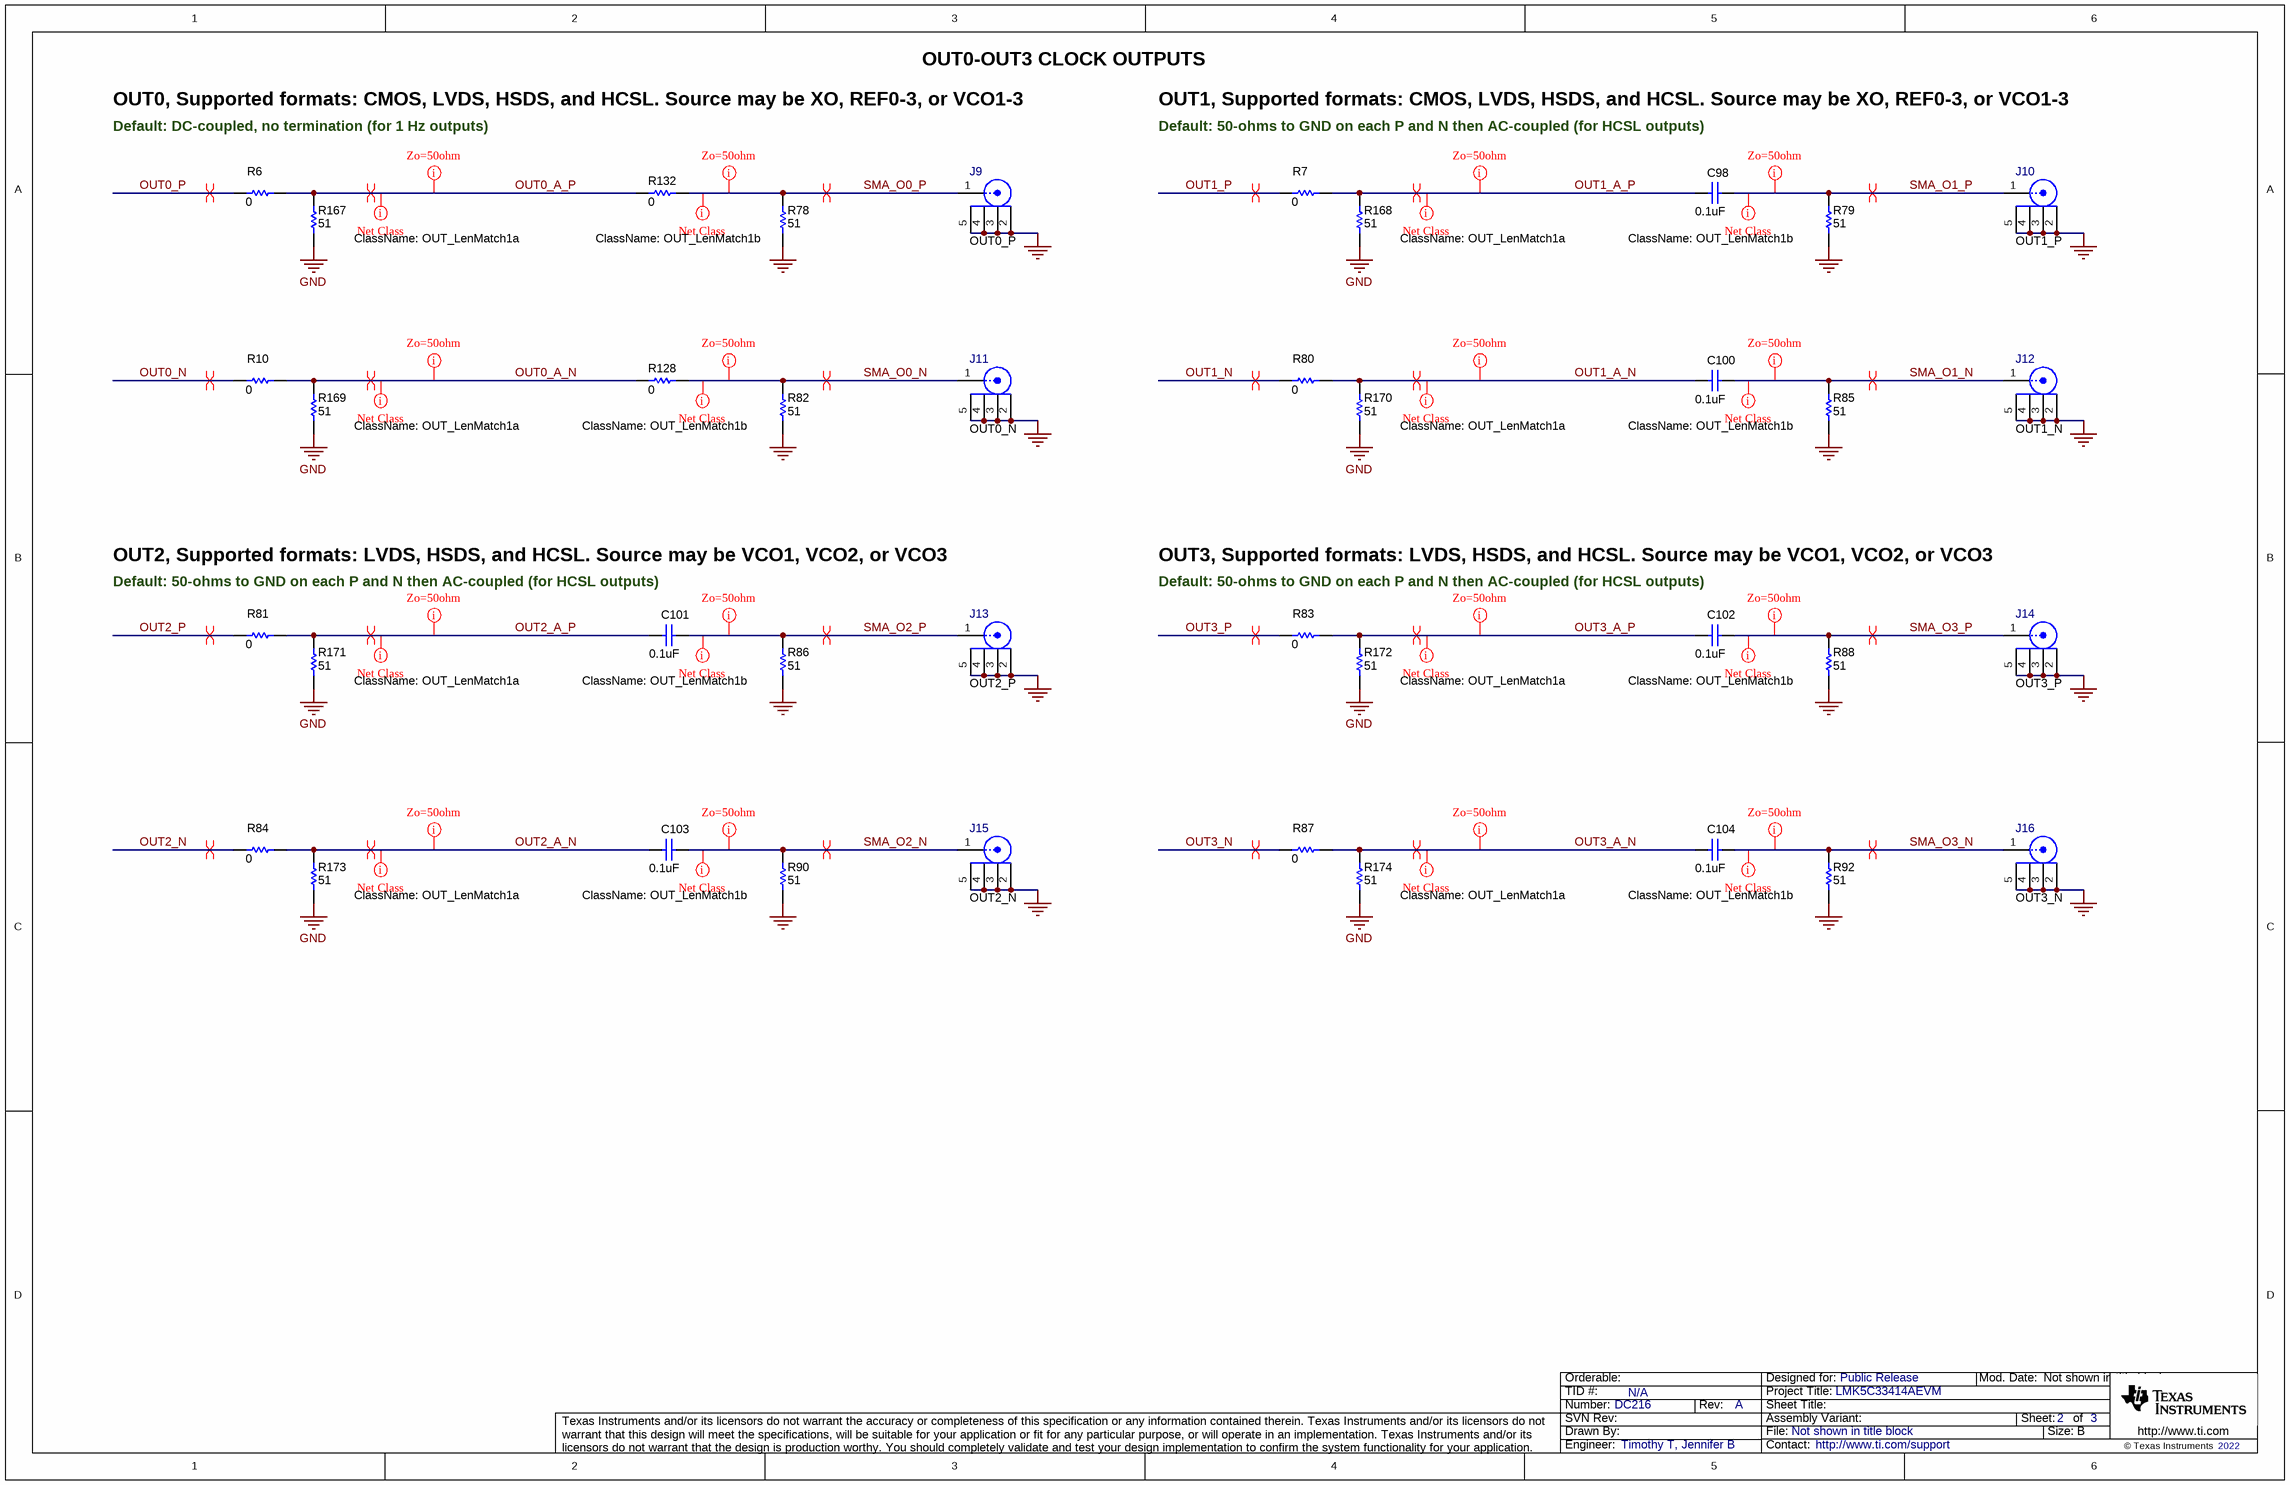
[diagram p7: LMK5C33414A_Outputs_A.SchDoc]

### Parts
C98  ValueDisplayed: 0.1uF  [0402L]  (hidden comment: GRM155R71E104KE14D)
C100  ValueDisplayed: 0.1uF  [0402L]  (hidden comment: GRM155R71E104KE14D)
C101  ValueDisplayed: 0.1uF  [0402L]  (hidden comment: GRM155R71E104KE14D)
C102  ValueDisplayed: 0.1uF  [0402L]  (hidden comment: GRM155R71E104KE14D)
C103  ValueDisplayed: 0.1uF  [0402L]  (hidden comment: GRM155R71E104KE14D)
C104  ValueDisplayed: 0.1uF  [0402L]  (hidden comment: GRM155R71E104KE14D)
J9  OUT0_P  [FP-CON-SMA-EDGE-S_CONN_JACK-MFG]
J10  OUT1_P  [FP-CON-SMA-EDGE-S_CONN_JACK-MFG]
J11  OUT0_N  [FP-CON-SMA-EDGE-S_CONN_JACK-MFG]
J12  OUT1_N  [FP-CON-SMA-EDGE-S_CONN_JACK-MFG]
J13  OUT2_P  [FP-CON-SMA-EDGE-S_CONN_JACK-MFG]
J14  OUT3_P  [FP-CON-SMA-EDGE-S_CONN_JACK-MFG]
J15  OUT2_N  [FP-CON-SMA-EDGE-S_CONN_JACK-MFG]
J16  OUT3_N  [FP-CON-SMA-EDGE-S_CONN_JACK-MFG]
R6  ValueDisplayed: 0  [0402L]  (hidden comment: RK73Z1ETTP)
R7  ValueDisplayed: 0  [0402L]  (hidden comment: RK73Z1ETTP)
R10  ValueDisplayed: 0  [0402L]  (hidden comment: RK73Z1ETTP)
R78  ValueDisplayed: 51  [0402L]  (hidden comment: RC0402JR-0751RL)
R79  ValueDisplayed: 51  [0402L]  (hidden comment: RC0402JR-0751RL)
R80  ValueDisplayed: 0  [0402L]  (hidden comment: RK73Z1ETTP)
R81  ValueDisplayed: 0  [0402L]  (hidden comment: RK73Z1ETTP)
R82  ValueDisplayed: 51  [0402L]  (hidden comment: RC0402JR-0751RL)
R83  ValueDisplayed: 0  [0402L]  (hidden comment: RK73Z1ETTP)
R84  ValueDisplayed: 0  [0402L]  (hidden comment: RK73Z1ETTP)
R85  ValueDisplayed: 51  [0402L]  (hidden comment: RC0402JR-0751RL)
R86  ValueDisplayed: 51  [0402L]  (hidden comment: RC0402JR-0751RL)
R87  ValueDisplayed: 0  [0402L]  (hidden comment: RK73Z1ETTP)
R88  ValueDisplayed: 51  [0402L]  (hidden comment: RC0402JR-0751RL)
R90  ValueDisplayed: 51  [0402L]  (hidden comment: RC0402JR-0751RL)
R92  ValueDisplayed: 51  [0402L]  (hidden comment: RC0402JR-0751RL)
R128  ValueDisplayed: 0  [0402L]  (hidden comment: RK73Z1ETTP)
R132  ValueDisplayed: 0  [0402L]  (hidden comment: RK73Z1ETTP)
R167  ValueDisplayed: 51  [0402L]  (hidden comment: RC0402JR-0751RL)
R168  ValueDisplayed: 51  [0402L]  (hidden comment: RC0402JR-0751RL)
R169  ValueDisplayed: 51  [0402L]  (hidden comment: RC0402JR-0751RL)
R170  ValueDisplayed: 51  [0402L]  (hidden comment: RC0402JR-0751RL)
R171  ValueDisplayed: 51  [0402L]  (hidden comment: RC0402JR-0751RL)
R172  ValueDisplayed: 51  [0402L]  (hidden comment: RC0402JR-0751RL)
R173  ValueDisplayed: 51  [0402L]  (hidden comment: RC0402JR-0751RL)
R174  ValueDisplayed: 51  [0402L]  (hidden comment: RC0402JR-0751RL)

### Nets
GND: J9.2 J9.3 J9.4 J9.5 J10.2 J10.3 J10.4 J10.5 J11.2 J11.3 J11.4 J11.5 J12.2 J12.3 J12.4 J12.5 J13.2 J13.3 J13.4 J13.5 J14.2 J14.3 J14.4 J14.5 J15.2 J15.3 J15.4 J15.5 J16.2 J16.3 J16.4 J16.5 R78.2 R79.2 R82.2 R85.2 R86.2 R88.2 R90.2 R92.2 R167.2 R168.2 R169.2 R170.2 R171.2 R172.2 R173.2 R174.2
OUT0_A_N: R10.2 R128.1 R169.1
OUT0_A_P: R6.2 R132.1 R167.1
OUT0_N: R10.1
OUT0_P: R6.1
OUT1_A_N: C100.2 R80.2 R170.1
OUT1_A_P: C98.2 R7.2 R168.1
OUT1_N: R80.1
OUT1_P: R7.1
OUT2_A_N: C103.2 R84.2 R173.1
OUT2_A_P: C101.2 R81.2 R171.1
OUT2_N: R84.1
OUT2_P: R81.1
OUT3_A_N: C104.2 R87.2 R174.1
OUT3_A_P: C102.2 R83.2 R172.1
OUT3_N: R87.1
OUT3_P: R83.1
SMA_O0_N: J11.1 R82.1 R128.2
SMA_O0_P: J9.1 R78.1 R132.2
SMA_O1_N: C100.1 J12.1 R85.1
SMA_O1_P: C98.1 J10.1 R79.1
SMA_O2_N: C103.1 J15.1 R90.1
SMA_O2_P: C101.1 J13.1 R86.1
SMA_O3_N: C104.1 J16.1 R92.1
SMA_O3_P: C102.1 J14.1 R88.1

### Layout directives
rule Impedance Constraint [Min = 45.00    Max = 55.00    ]: OUT0_A_N, OUT0_A_P, OUT1_A_N, OUT1_A_P, OUT2_A_N, OUT2_A_P, OUT3_A_N, OUT3_A_P, SMA_O0_N, SMA_O0_P, SMA_O1_N, SMA_O1_P, SMA_O2_N, SMA_O2_P, SMA_O3_N, SMA_O3_P
differential pair: OUT0_A_N, OUT0_A_P, OUT0_N, OUT0_P, OUT1_A_N, OUT1_A_P, OUT1_N, OUT1_P, OUT2_A_N, OUT2_A_P, OUT2_N, OUT2_P, OUT3_A_N, OUT3_A_P, OUT3_N, OUT3_P, SMA_O0_N, SMA_O0_P, SMA_O1_N, SMA_O1_P, SMA_O2_N, SMA_O2_P, SMA_O3_N, SMA_O3_P
net class OUT_LenMatch1a: OUT0_A_N, OUT0_A_P, OUT1_A_N, OUT1_A_P, OUT2_A_N, OUT2_A_P, OUT3_A_N, OUT3_A_P
net class OUT_LenMatch1b: SMA_O0_N, SMA_O0_P, SMA_O1_N, SMA_O1_P, SMA_O2_N, SMA_O2_P, SMA_O3_N, SMA_O3_P

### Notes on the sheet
- OUT0, Supported formats: CMOS, LVDS, HSDS, and HCSL. Source may be XO, REF0-3, or VCO1-3
- OUT0-OUT3 CLOCK OUTPUTS
- OUT1, Supported formats: CMOS, LVDS, HSDS, and HCSL. Source may be XO, REF0-3, or VCO1-3
- Default: DC-coupled, no termination (for 1 Hz outputs)
- Default: 50-ohms to GND on each P and N then AC-coupled (for HCSL outputs)
- OUT2, Supported formats: LVDS, HSDS, and HCSL. Source may be VCO1, VCO2, or VCO3
- OUT3, Supported formats: LVDS, HSDS, and HCSL. Source may be VCO1, VCO2, or VCO3

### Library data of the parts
C98 C100-C104 = CMP-0006659-2: CAP, CERM, 0.1 uF, 25 V, +/- 10%, X7R, 0402; Manufacturer: MuRata; TaMin_C: -55°C; Polarized: N; SizeAreaWB_mm2: 3; Value1: Unknown; U/M: EA; Value: 0.1uF; TaMax_C: 125°C; SizeZ_mm: 0.6; SizeX_mm: 1; SizeY_mm: 0.5; Cap_Case: 0402; Value2: 25V; CompType: Capacitor; Cap_F: 100nF; AEC Category: Q200
J9-J16 = CMP-0088000-4: CONN SMA JACK STR EDGE MNT; Manufacturer: RF Solutions Ltd.; PartNumber: CON-SMA-EDGE-S; ContactFinish: Gold; Shrouded: true
R6 R7 R10 R80 R81 R83 R84 R87 = CMP-0027007-2: RES, 0, 5%, 0.063 W, AEC-Q200 Grade 0, 0402; Manufacturer: KOA Speer; Power_W: 63mW; TempCo: ppm/C; Value_Code: 0000; U/M: EA; Value: 0; EIA_Code: E24; SizeX_mm: 1; SizeY_mm: 0.5; SizeZ_mm: 0.6; Value2: 0.063W; CompType: Resistor; AEC Qualified: Y; AEC Category: Q200
R78 R79 R82 R85 R86 R88 R90 R92 R167-R174 = CMP-0027006-2: RES, 51, 5%, 0.0625 W, 0402; Manufacturer: Yageo America; Value: 51; Value_Code: 51R0; Power_W: 62.5mW; VDC_V: 50V; TempCo: 100 ppm/C; EIA_Code: E24; AEC Category: Q200; AEC Qualified: N; SizeArea_mm2: 0.5; SizeX_mm: 1; SizeZ_mm: 0.6; U/M: EA
R128 = CMP-0027007-2: RES, 0, 5%, 0.063 W, AEC-Q200 Grade 0, 0402; Manufacturer: KOA Speer; TempCo: ppm/C; U/M: EA; Value: 0; SizeZ_mm: 0.6; SizeX_mm: 1; SizeY_mm: 0.5; Value2: 0.063W; CompType: Resistor; AEC Qualified: Y; AEC Category: Q200; Power_W: 63mW; Value_Code: 0000; EIA_Code: E24
R132 = CMP-0027007-2: RES, 0, 5%, 0.063 W, AEC-Q200 Grade 0, 0402; Manufacturer: KOA Speer; TempCo: ppm/C; U/M: EA; Value: 0; SizeZ_mm: 0.6; SizeX_mm: 1; SizeY_mm: 0.5; Value2: 0.063W; AEC Qualified: Y; AEC Category: Q200; Power_W: 63mW; Value_Code: 0000; EIA_Code: E24

## Sheet LMK5C33414A_Outputs_B.SchDoc
size 431 x 279 mm; Date: Not shown in title block; ApprovedBy: Not shown in title block; CheckedBy: Not shown in title block; Author: Not shown in title block; CompanyName: Not shown in title block; Engineer: Not shown in title block; Organization: Not shown in title block; Address1: Not shown in title block; Address2: Not shown in title block; Address3: Not shown in title block; Address4: Not shown in title block; DocumentNumber: 2; Revision: Use project parameter SCH_Rev; SheetNumber: 2; SheetTotal: 3; PageSetup: Record=PageOptions¦CenterHorizontal=True¦CenterVertical=True¦PrintScale=1.00¦XCorrection=1.00¦YCorrection=1.00¦PrintKind=0¦BorderSize=5000000¦LeftOffset=0¦BottomOffset=0¦Orientation=2¦PaperLength=1000¦PaperWidth=1000¦Scale=100¦PaperSource=15¦PrintQuality=600¦MediaType=1¦DitherType=10¦PaperKind=Letter¦PrintScaleMode=1
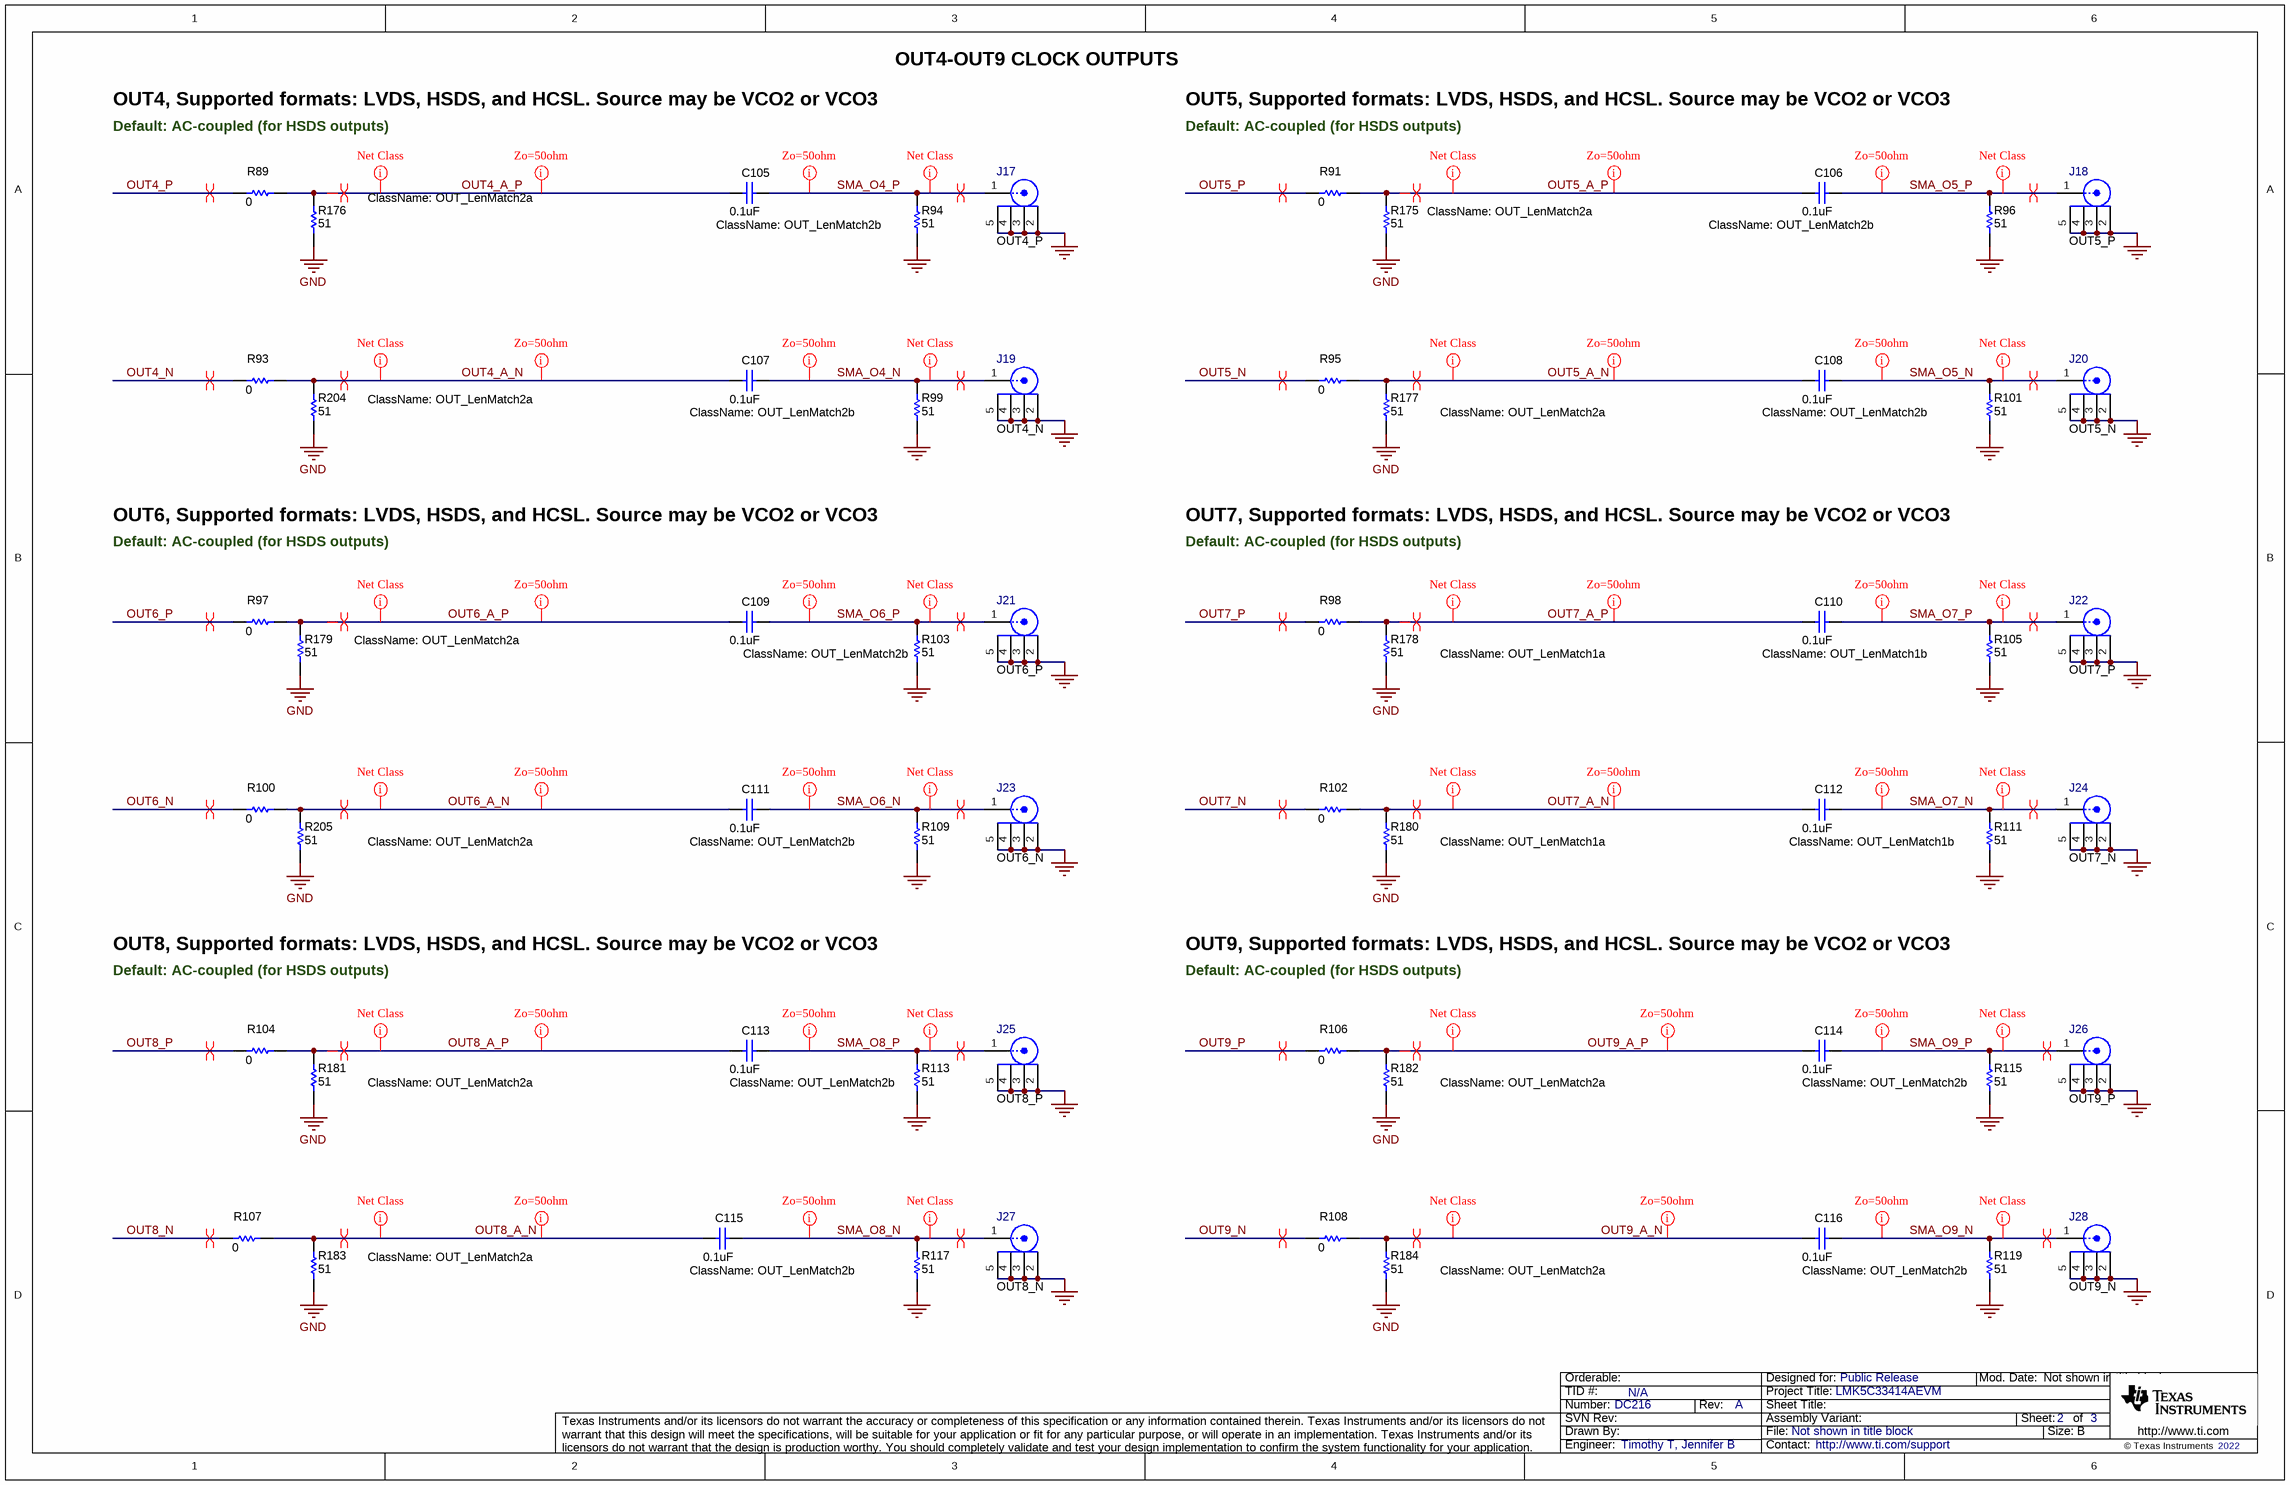
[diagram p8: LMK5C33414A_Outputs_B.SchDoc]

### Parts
C105  ValueDisplayed: 0.1uF  [0402L]  (hidden comment: GRM155R71E104KE14D)
C106  ValueDisplayed: 0.1uF  [0402L]  (hidden comment: GRM155R71E104KE14D)
C107  ValueDisplayed: 0.1uF  [0402L]  (hidden comment: GRM155R71E104KE14D)
C108  ValueDisplayed: 0.1uF  [0402L]  (hidden comment: GRM155R71E104KE14D)
C109  ValueDisplayed: 0.1uF  [0402L]  (hidden comment: GRM155R71E104KE14D)
C110  ValueDisplayed: 0.1uF  [0402L]  (hidden comment: GRM155R71E104KE14D)
C111  ValueDisplayed: 0.1uF  [0402L]  (hidden comment: GRM155R71E104KE14D)
C112  ValueDisplayed: 0.1uF  [0402L]  (hidden comment: GRM155R71E104KE14D)
C113  ValueDisplayed: 0.1uF  [0402L]  (hidden comment: GRM155R71E104KE14D)
C114  ValueDisplayed: 0.1uF  [0402L]  (hidden comment: GRM155R71E104KE14D)
C115  ValueDisplayed: 0.1uF  [0402L]  (hidden comment: GRM155R71E104KE14D)
C116  ValueDisplayed: 0.1uF  [0402L]  (hidden comment: GRM155R71E104KE14D)
J17  OUT4_P  [FP-CON-SMA-EDGE-S_CONN_JACK-MFG]
J18  OUT5_P  [FP-CON-SMA-EDGE-S_CONN_JACK-MFG]
J19  OUT4_N  [FP-CON-SMA-EDGE-S_CONN_JACK-MFG]
J20  OUT5_N  [FP-CON-SMA-EDGE-S_CONN_JACK-MFG]
J21  OUT6_P  [FP-CON-SMA-EDGE-S_CONN_JACK-MFG]
J22  OUT7_P  [FP-CON-SMA-EDGE-S_CONN_JACK-MFG]
J23  OUT6_N  [FP-CON-SMA-EDGE-S_CONN_JACK-MFG]
J24  OUT7_N  [FP-CON-SMA-EDGE-S_CONN_JACK-MFG]
J25  OUT8_P  [FP-CON-SMA-EDGE-S_CONN_JACK-MFG]
J26  OUT9_P  [FP-CON-SMA-EDGE-S_CONN_JACK-MFG]
J27  OUT8_N  [FP-CON-SMA-EDGE-S_CONN_JACK-MFG]
J28  OUT9_N  [FP-CON-SMA-EDGE-S_CONN_JACK-MFG]
R89  ValueDisplayed: 0  [0402L]  (hidden comment: RK73Z1ETTP)
R91  ValueDisplayed: 0  [0402L]  (hidden comment: RK73Z1ETTP)
R93  ValueDisplayed: 0  [0402L]  (hidden comment: RK73Z1ETTP)
R94  ValueDisplayed: 51  [0402L]  (hidden comment: RC0402JR-0751RL)
R95  ValueDisplayed: 0  [0402L]  (hidden comment: RK73Z1ETTP)
R96  ValueDisplayed: 51  [0402L]  (hidden comment: RC0402JR-0751RL)
R97  ValueDisplayed: 0  [0402L]  (hidden comment: RK73Z1ETTP)
R98  ValueDisplayed: 0  [0402L]  (hidden comment: RK73Z1ETTP)
R99  ValueDisplayed: 51  [0402L]  (hidden comment: RC0402JR-0751RL)
R100  ValueDisplayed: 0  [0402L]  (hidden comment: RK73Z1ETTP)
R101  ValueDisplayed: 51  [0402L]  (hidden comment: RC0402JR-0751RL)
R102  ValueDisplayed: 0  [0402L]  (hidden comment: RK73Z1ETTP)
R103  ValueDisplayed: 51  [0402L]  (hidden comment: RC0402JR-0751RL)
R104  ValueDisplayed: 0  [0402L]  (hidden comment: RK73Z1ETTP)
R105  ValueDisplayed: 51  [0402L]  (hidden comment: RC0402JR-0751RL)
R106  ValueDisplayed: 0  [0402L]  (hidden comment: RK73Z1ETTP)
R107  ValueDisplayed: 0  [0402L]  (hidden comment: RK73Z1ETTP)
R108  ValueDisplayed: 0  [0402L]  (hidden comment: RK73Z1ETTP)
R109  ValueDisplayed: 51  [0402L]  (hidden comment: RC0402JR-0751RL)
R111  ValueDisplayed: 51  [0402L]  (hidden comment: RC0402JR-0751RL)
R113  ValueDisplayed: 51  [0402L]  (hidden comment: RC0402JR-0751RL)
R115  ValueDisplayed: 51  [0402L]  (hidden comment: RC0402JR-0751RL)
R117  ValueDisplayed: 51  [0402L]  (hidden comment: RC0402JR-0751RL)
R119  ValueDisplayed: 51  [0402L]  (hidden comment: RC0402JR-0751RL)
R175  ValueDisplayed: 51  [0402L]  (hidden comment: RC0402JR-0751RL)
R176  ValueDisplayed: 51  [0402L]  (hidden comment: RC0402JR-0751RL)
R177  ValueDisplayed: 51  [0402L]  (hidden comment: RC0402JR-0751RL)
R178  ValueDisplayed: 51  [0402L]  (hidden comment: RC0402JR-0751RL)
R179  ValueDisplayed: 51  [0402L]  (hidden comment: RC0402JR-0751RL)
R180  ValueDisplayed: 51  [0402L]  (hidden comment: RC0402JR-0751RL)
R181  ValueDisplayed: 51  [0402L]  (hidden comment: RC0402JR-0751RL)
R182  ValueDisplayed: 51  [0402L]  (hidden comment: RC0402JR-0751RL)
R183  ValueDisplayed: 51  [0402L]  (hidden comment: RC0402JR-0751RL)
R184  ValueDisplayed: 51  [0402L]  (hidden comment: RC0402JR-0751RL)
R204  ValueDisplayed: 51  [0402L]  (hidden comment: RC0402JR-0751RL)
R205  ValueDisplayed: 51  [0402L]  (hidden comment: RC0402JR-0751RL)

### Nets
GND: J17.2 J17.3 J17.4 J17.5 J18.2 J18.3 J18.4 J18.5 J19.2 J19.3 J19.4 J19.5 J20.2 J20.3 J20.4 J20.5 J21.2 J21.3 J21.4 J21.5 J22.2 J22.3 J22.4 J22.5 J23.2 J23.3 J23.4 J23.5 J24.2 J24.3 J24.4 J24.5 J25.2 J25.3 J25.4 J25.5 J26.2 J26.3 J26.4 J26.5 J27.2 J27.3 J27.4 J27.5 J28.2 J28.3 J28.4 J28.5 R94.2 R96.2 R99.2 R101.2 R103.2 R105.2 R109.2 R111.2 R113.2 R115.2 R117.2 R119.2 R175.2 R176.2 R177.2 R178.2 R179.2 R180.2 R181.2 R182.2 R183.2 R184.2 R204.2 R205.2
OUT4_A_N: C107.2 R93.2 R204.1
OUT4_A_P: C105.2 R89.2 R176.1
OUT4_N: R93.1
OUT4_P: R89.1
OUT5_A_N: C108.2 R95.2 R177.1
OUT5_A_P: C106.2 R91.2 R175.1
OUT5_N: R95.1
OUT5_P: R91.1
OUT6_A_N: C111.2 R100.2 R205.1
OUT6_A_P: C109.2 R97.2 R179.1
OUT6_N: R100.1
OUT6_P: R97.1
OUT7_A_N: C112.2 R102.2 R180.1
OUT7_A_P: C110.2 R98.2 R178.1
OUT7_N: R102.1
OUT7_P: R98.1
OUT8_A_N: C115.2 R107.2 R183.1
OUT8_A_P: C113.2 R104.2 R181.1
OUT8_N: R107.1
OUT8_P: R104.1
OUT9_A_N: C116.2 R108.2 R184.1
OUT9_A_P: C114.2 R106.2 R182.1
OUT9_N: R108.1
OUT9_P: R106.1
SMA_O4_N: C107.1 J19.1 R99.1
SMA_O4_P: C105.1 J17.1 R94.1
SMA_O5_N: C108.1 J20.1 R101.1
SMA_O5_P: C106.1 J18.1 R96.1
SMA_O6_N: C111.1 J23.1 R109.1
SMA_O6_P: C109.1 J21.1 R103.1
SMA_O7_N: C112.1 J24.1 R111.1
SMA_O7_P: C110.1 J22.1 R105.1
SMA_O8_N: C115.1 J27.1 R117.1
SMA_O8_P: C113.1 J25.1 R113.1
SMA_O9_N: C116.1 J28.1 R119.1
SMA_O9_P: C114.1 J26.1 R115.1

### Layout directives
rule Impedance Constraint [Min = 45.00    Max = 55.00    ]: OUT4_A_N, OUT4_A_P, OUT5_A_N, OUT5_A_P, OUT6_A_N, OUT6_A_P, OUT7_A_N, OUT7_A_P, OUT8_A_N, OUT8_A_P, OUT9_A_N, OUT9_A_P, SMA_O4_N, SMA_O4_P, SMA_O5_N, SMA_O5_P, SMA_O6_N, SMA_O6_P, SMA_O7_N, SMA_O7_P, SMA_O8_N, SMA_O8_P, SMA_O9_N, SMA_O9_P
differential pair: OUT4_A_N, OUT4_A_P, OUT4_N, OUT4_P, OUT5_A_N, OUT5_A_P, OUT5_N, OUT5_P, OUT6_A_N, OUT6_A_P, OUT6_N, OUT6_P, OUT7_A_N, OUT7_A_P, OUT7_N, OUT7_P, OUT8_A_N, OUT8_A_P, OUT8_N, OUT8_P, OUT9_A_N, OUT9_A_P, OUT9_N, OUT9_P, SMA_O4_N, SMA_O4_P, SMA_O5_N, SMA_O5_P, SMA_O6_N, SMA_O6_P, SMA_O7_N, SMA_O7_P, SMA_O8_N, SMA_O8_P, SMA_O9_N, SMA_O9_P
net class OUT_LenMatch2a: OUT4_A_N, OUT4_A_P, OUT5_A_N, OUT5_A_P, OUT6_A_N, OUT6_A_P, OUT8_A_N, OUT8_A_P, OUT9_A_N, OUT9_A_P
net class OUT_LenMatch1a: OUT7_A_N, OUT7_A_P
net class OUT_LenMatch2b: SMA_O4_N, SMA_O4_P, SMA_O5_N, SMA_O5_P, SMA_O6_N, SMA_O6_P, SMA_O8_N, SMA_O8_P, SMA_O9_N, SMA_O9_P
net class OUT_LenMatch1b: SMA_O7_N, SMA_O7_P

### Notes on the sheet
- OUT4, Supported formats: LVDS, HSDS, and HCSL. Source may be VCO2 or VCO3
- OUT4-OUT9 CLOCK OUTPUTS
- OUT5, Supported formats: LVDS, HSDS, and HCSL. Source may be VCO2 or VCO3
- Default: AC-coupled (for HSDS outputs)
- OUT6, Supported formats: LVDS, HSDS, and HCSL. Source may be VCO2 or VCO3
- OUT7, Supported formats: LVDS, HSDS, and HCSL. Source may be VCO2 or VCO3
- OUT8, Supported formats: LVDS, HSDS, and HCSL. Source may be VCO2 or VCO3
- OUT9, Supported formats: LVDS, HSDS, and HCSL. Source may be VCO2 or VCO3

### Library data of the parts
C105-C116 = CMP-0006659-2: as C98 on sheet LMK5C33414A_Outputs_A
J17-J28 = CMP-0088000-4: as J9-J16 on sheet LMK5C33414A_Outputs_A
R89 R91 R93 R95 R97 R98 R100 R102 R104 R106-R108 = CMP-0027007-2: as R6 on sheet LMK5C33414A_Outputs_A
R94 R96 R99 R101 R103 R105 R109 R111 R113 R115 R117 R119 R175-R184 R204 R205 = CMP-0027006-2: as R78 on sheet LMK5C33414A_Outputs_A

## Sheet LMK5C33414A_Outputs_C.SchDoc
size 431 x 279 mm; Date: Not shown in title block; ApprovedBy: Not shown in title block; CheckedBy: Not shown in title block; Author: Not shown in title block; CompanyName: Not shown in title block; Engineer: Not shown in title block; Organization: Not shown in title block; Address1: Not shown in title block; Address2: Not shown in title block; Address3: Not shown in title block; Address4: Not shown in title block; DocumentNumber: 2; Revision: Use project parameter SCH_Rev; SheetNumber: 2; SheetTotal: 3; PageSetup: Record=PageOptions¦CenterHorizontal=True¦CenterVertical=True¦PrintScale=1.00¦XCorrection=1.00¦YCorrection=1.00¦PrintKind=0¦BorderSize=5000000¦LeftOffset=0¦BottomOffset=0¦Orientation=2¦PaperLength=1000¦PaperWidth=1000¦Scale=100¦PaperSource=15¦PrintQuality=600¦MediaType=1¦DitherType=10¦PaperKind=Letter¦PrintScaleMode=1
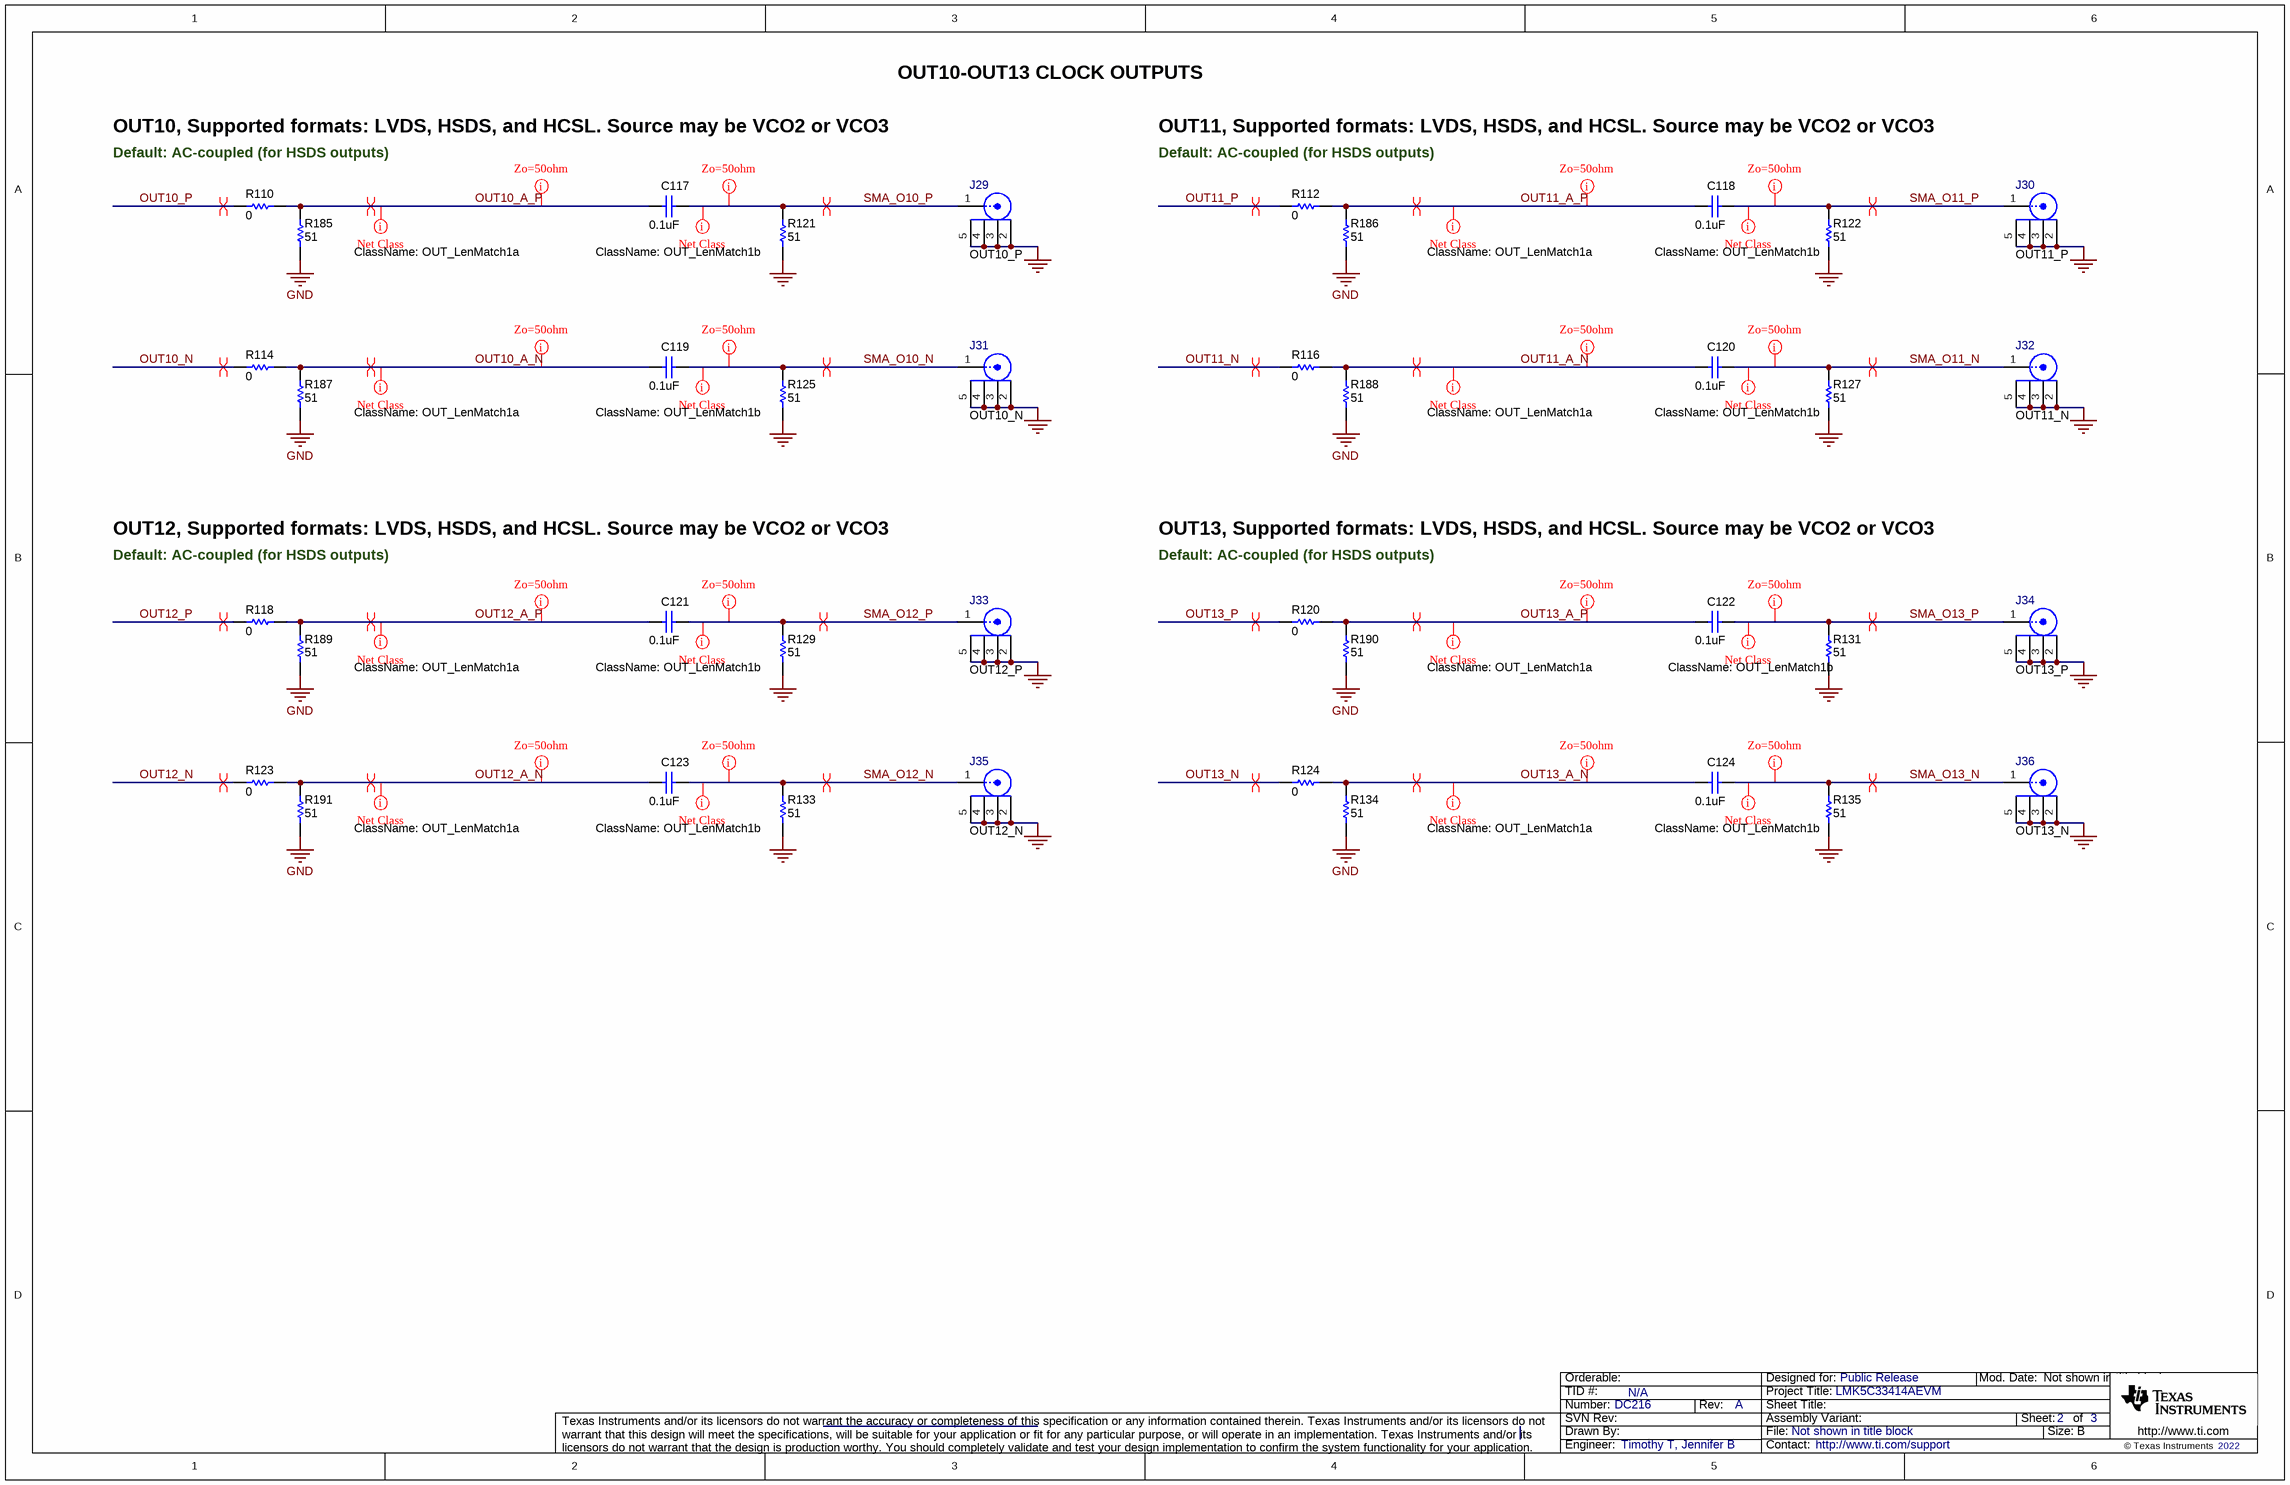
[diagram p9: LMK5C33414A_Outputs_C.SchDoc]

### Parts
C117  ValueDisplayed: 0.1uF  [0402L]  (hidden comment: GRM155R71E104KE14D)
C118  ValueDisplayed: 0.1uF  [0402L]  (hidden comment: GRM155R71E104KE14D)
C119  ValueDisplayed: 0.1uF  [0402L]  (hidden comment: GRM155R71E104KE14D)
C120  ValueDisplayed: 0.1uF  [0402L]  (hidden comment: GRM155R71E104KE14D)
C121  ValueDisplayed: 0.1uF  [0402L]  (hidden comment: GRM155R71E104KE14D)
C122  ValueDisplayed: 0.1uF  [0402L]  (hidden comment: GRM155R71E104KE14D)
C123  ValueDisplayed: 0.1uF  [0402L]  (hidden comment: GRM155R71E104KE14D)
C124  ValueDisplayed: 0.1uF  [0402L]  (hidden comment: GRM155R71E104KE14D)
J29  OUT10_P  [FP-CON-SMA-EDGE-S_CONN_JACK-MFG]
J30  OUT11_P  [FP-CON-SMA-EDGE-S_CONN_JACK-MFG]
J31  OUT10_N  [FP-CON-SMA-EDGE-S_CONN_JACK-MFG]
J32  OUT11_N  [FP-CON-SMA-EDGE-S_CONN_JACK-MFG]
J33  OUT12_P  [FP-CON-SMA-EDGE-S_CONN_JACK-MFG]
J34  OUT13_P  [FP-CON-SMA-EDGE-S_CONN_JACK-MFG]
J35  OUT12_N  [FP-CON-SMA-EDGE-S_CONN_JACK-MFG]
J36  OUT13_N  [FP-CON-SMA-EDGE-S_CONN_JACK-MFG]
R110  ValueDisplayed: 0  [0402L]  (hidden comment: RK73Z1ETTP)
R112  ValueDisplayed: 0  [0402L]  (hidden comment: RK73Z1ETTP)
R114  ValueDisplayed: 0  [0402L]  (hidden comment: RK73Z1ETTP)
R116  ValueDisplayed: 0  [0402L]  (hidden comment: RK73Z1ETTP)
R118  ValueDisplayed: 0  [0402L]  (hidden comment: RK73Z1ETTP)
R120  ValueDisplayed: 0  [0402L]  (hidden comment: RK73Z1ETTP)
R121  ValueDisplayed: 51  [0402L]  (hidden comment: RC0402JR-0751RL)
R122  ValueDisplayed: 51  [0402L]  (hidden comment: RC0402JR-0751RL)
R123  ValueDisplayed: 0  [0402L]  (hidden comment: RK73Z1ETTP)
R124  ValueDisplayed: 0  [0402L]  (hidden comment: RK73Z1ETTP)
R125  ValueDisplayed: 51  [0402L]  (hidden comment: RC0402JR-0751RL)
R127  ValueDisplayed: 51  [0402L]  (hidden comment: RC0402JR-0751RL)
R129  ValueDisplayed: 51  [0402L]  (hidden comment: RC0402JR-0751RL)
R131  ValueDisplayed: 51  [0402L]  (hidden comment: RC0402JR-0751RL)
R133  ValueDisplayed: 51  [0402L]  (hidden comment: RC0402JR-0751RL)
R134  ValueDisplayed: 51  [0402L]  (hidden comment: RC0402JR-0751RL)
R135  ValueDisplayed: 51  [0402L]  (hidden comment: RC0402JR-0751RL)
R185  ValueDisplayed: 51  [0402L]  (hidden comment: RC0402JR-0751RL)
R186  ValueDisplayed: 51  [0402L]  (hidden comment: RC0402JR-0751RL)
R187  ValueDisplayed: 51  [0402L]  (hidden comment: RC0402JR-0751RL)
R188  ValueDisplayed: 51  [0402L]  (hidden comment: RC0402JR-0751RL)
R189  ValueDisplayed: 51  [0402L]  (hidden comment: RC0402JR-0751RL)
R190  ValueDisplayed: 51  [0402L]  (hidden comment: RC0402JR-0751RL)
R191  ValueDisplayed: 51  [0402L]  (hidden comment: RC0402JR-0751RL)

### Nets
GND: J29.2 J29.3 J29.4 J29.5 J30.2 J30.3 J30.4 J30.5 J31.2 J31.3 J31.4 J31.5 J32.2 J32.3 J32.4 J32.5 J33.2 J33.3 J33.4 J33.5 J34.2 J34.3 J34.4 J34.5 J35.2 J35.3 J35.4 J35.5 J36.2 J36.3 J36.4 J36.5 R121.2 R122.2 R125.2 R127.2 R129.2 R131.2 R133.2 R134.2 R135.2 R185.2 R186.2 R187.2 R188.2 R189.2 R190.2 R191.2
OUT10_A_N: C119.2 R114.2 R187.1
OUT10_A_P: C117.2 R110.2 R185.1
OUT10_N: R114.1
OUT10_P: R110.1
OUT11_A_N: C120.2 R116.2 R188.1
OUT11_A_P: C118.2 R112.2 R186.1
OUT11_N: R116.1
OUT11_P: R112.1
OUT12_A_N: C123.2 R123.2 R191.1
OUT12_A_P: C121.2 R118.2 R189.1
OUT12_N: R123.1
OUT12_P: R118.1
OUT13_A_N: C124.2 R124.2 R134.1
OUT13_A_P: C122.2 R120.2 R190.1
OUT13_N: R124.1
OUT13_P: R120.1
SMA_O10_N: C119.1 J31.1 R125.1
SMA_O10_P: C117.1 J29.1 R121.1
SMA_O11_N: C120.1 J32.1 R127.1
SMA_O11_P: C118.1 J30.1 R122.1
SMA_O12_N: C123.1 J35.1 R133.1
SMA_O12_P: C121.1 J33.1 R129.1
SMA_O13_N: C124.1 J36.1 R135.1
SMA_O13_P: C122.1 J34.1 R131.1

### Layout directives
rule Impedance Constraint [Min = 45.00    Max = 55.00    ]: OUT10_A_N, OUT10_A_P, OUT11_A_N, OUT11_A_P, OUT12_A_N, OUT12_A_P, OUT13_A_N, OUT13_A_P, SMA_O10_N, SMA_O10_P, SMA_O11_N, SMA_O11_P, SMA_O12_N, SMA_O12_P, SMA_O13_N, SMA_O13_P
differential pair: OUT10_A_N, OUT10_A_P, OUT10_N, OUT10_P, OUT11_A_N, OUT11_A_P, OUT11_N, OUT11_P, OUT12_A_N, OUT12_A_P, OUT12_N, OUT12_P, OUT13_A_N, OUT13_A_P, OUT13_N, OUT13_P, SMA_O10_N, SMA_O10_P, SMA_O11_N, SMA_O11_P, SMA_O12_N, SMA_O12_P, SMA_O13_N, SMA_O13_P
net class OUT_LenMatch1a: OUT10_A_N, OUT10_A_P, OUT11_A_N, OUT11_A_P, OUT12_A_N, OUT12_A_P, OUT13_A_N, OUT13_A_P
net class OUT_LenMatch1b: SMA_O10_N, SMA_O10_P, SMA_O11_N, SMA_O11_P, SMA_O12_N, SMA_O12_P, SMA_O13_N, SMA_O13_P

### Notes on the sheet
- OUT10-OUT13 CLOCK OUTPUTS
- OUT10, Supported formats: LVDS, HSDS, and HCSL. Source may be VCO2 or VCO3
- Default: AC-coupled (for HSDS outputs)
- OUT11, Supported formats: LVDS, HSDS, and HCSL. Source may be VCO2 or VCO3
- OUT12, Supported formats: LVDS, HSDS, and HCSL. Source may be VCO2 or VCO3
- OUT13, Supported formats: LVDS, HSDS, and HCSL. Source may be VCO2 or VCO3

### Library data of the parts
C117-C124 = CMP-0006659-2: as C98 on sheet LMK5C33414A_Outputs_A
J29-J36 = CMP-0088000-4: as J9-J16 on sheet LMK5C33414A_Outputs_A
R110 R112 R114 R116 R118 R120 R123 R124 = CMP-0027007-2: as R6 on sheet LMK5C33414A_Outputs_A
R121 R122 R125 R127 R129 R131 R133-R135 R185-R191 = CMP-0027006-2: as R78 on sheet LMK5C33414A_Outputs_A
